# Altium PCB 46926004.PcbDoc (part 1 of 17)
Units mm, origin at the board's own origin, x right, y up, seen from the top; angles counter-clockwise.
Board outline 250 x 200 mm, 6 copper layers (Top Layer, INT1_GND, INT2_SIG, INT3_SIG, INT4_GND, Bottom Layer), stack 1.71 mm thick; 1450 components, 1293 nets, 5656 pads, 2307 vias.
Unrouted connection lines stored in the file: 2.
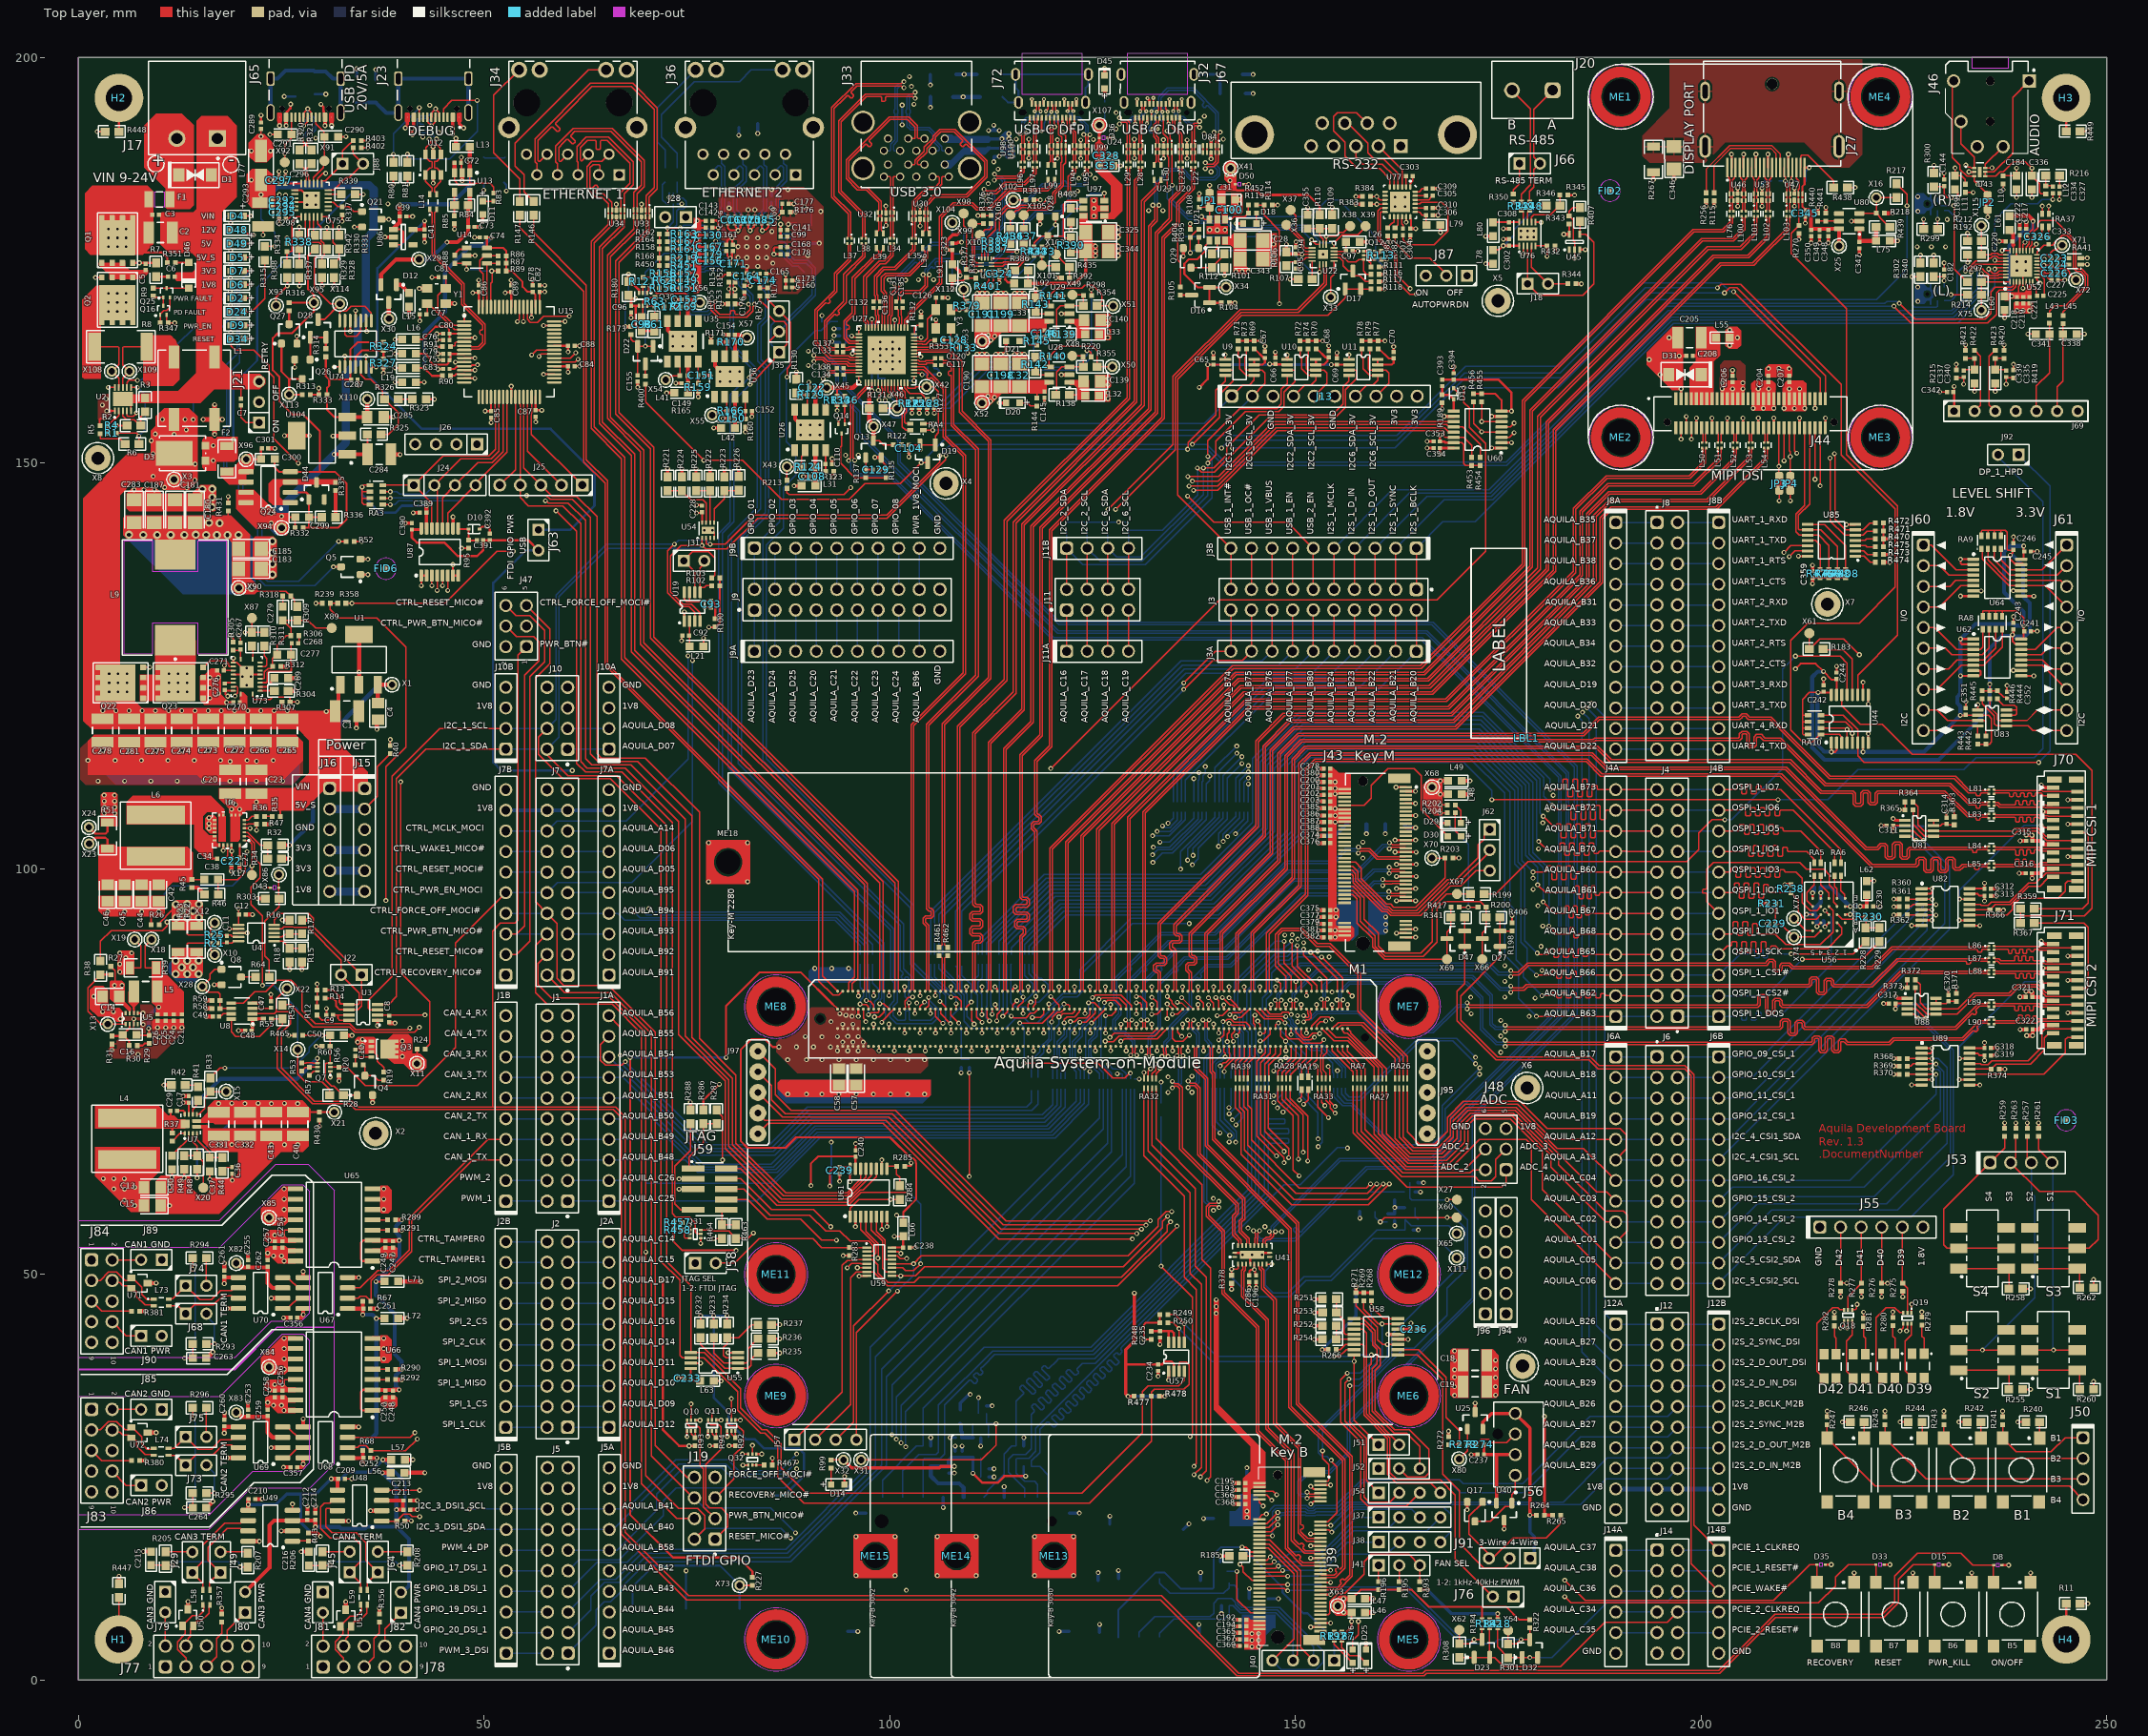
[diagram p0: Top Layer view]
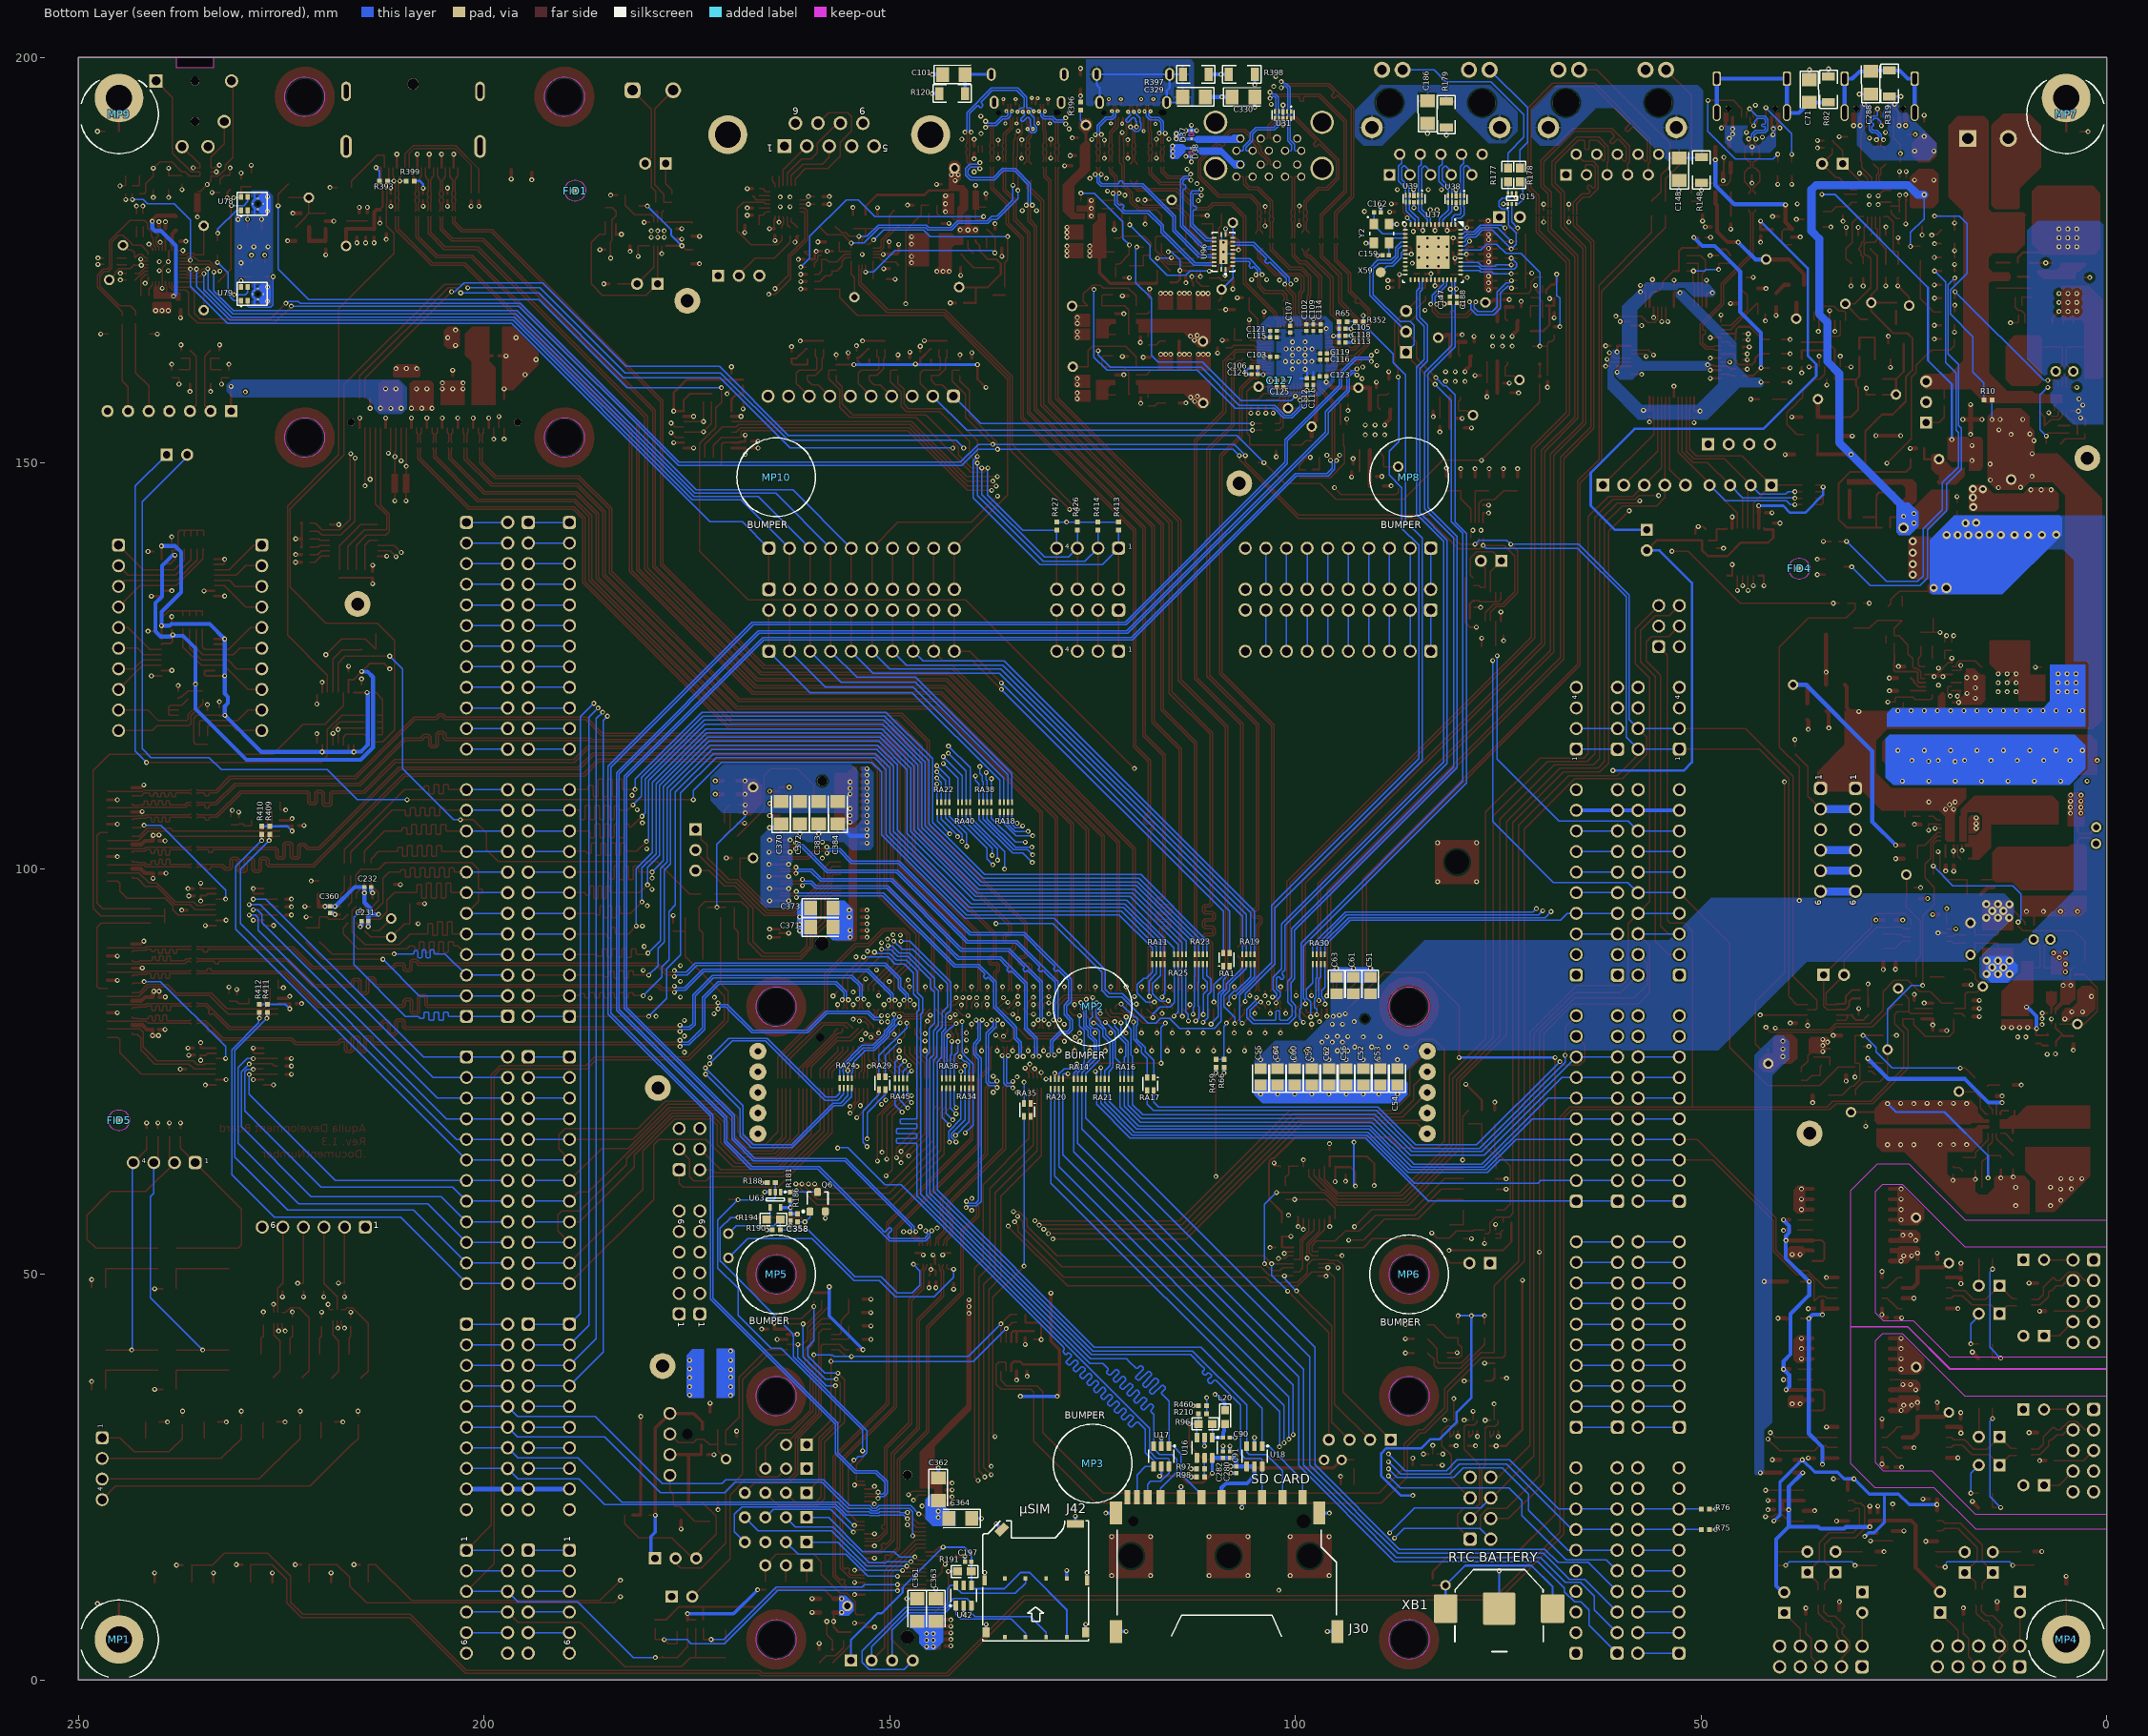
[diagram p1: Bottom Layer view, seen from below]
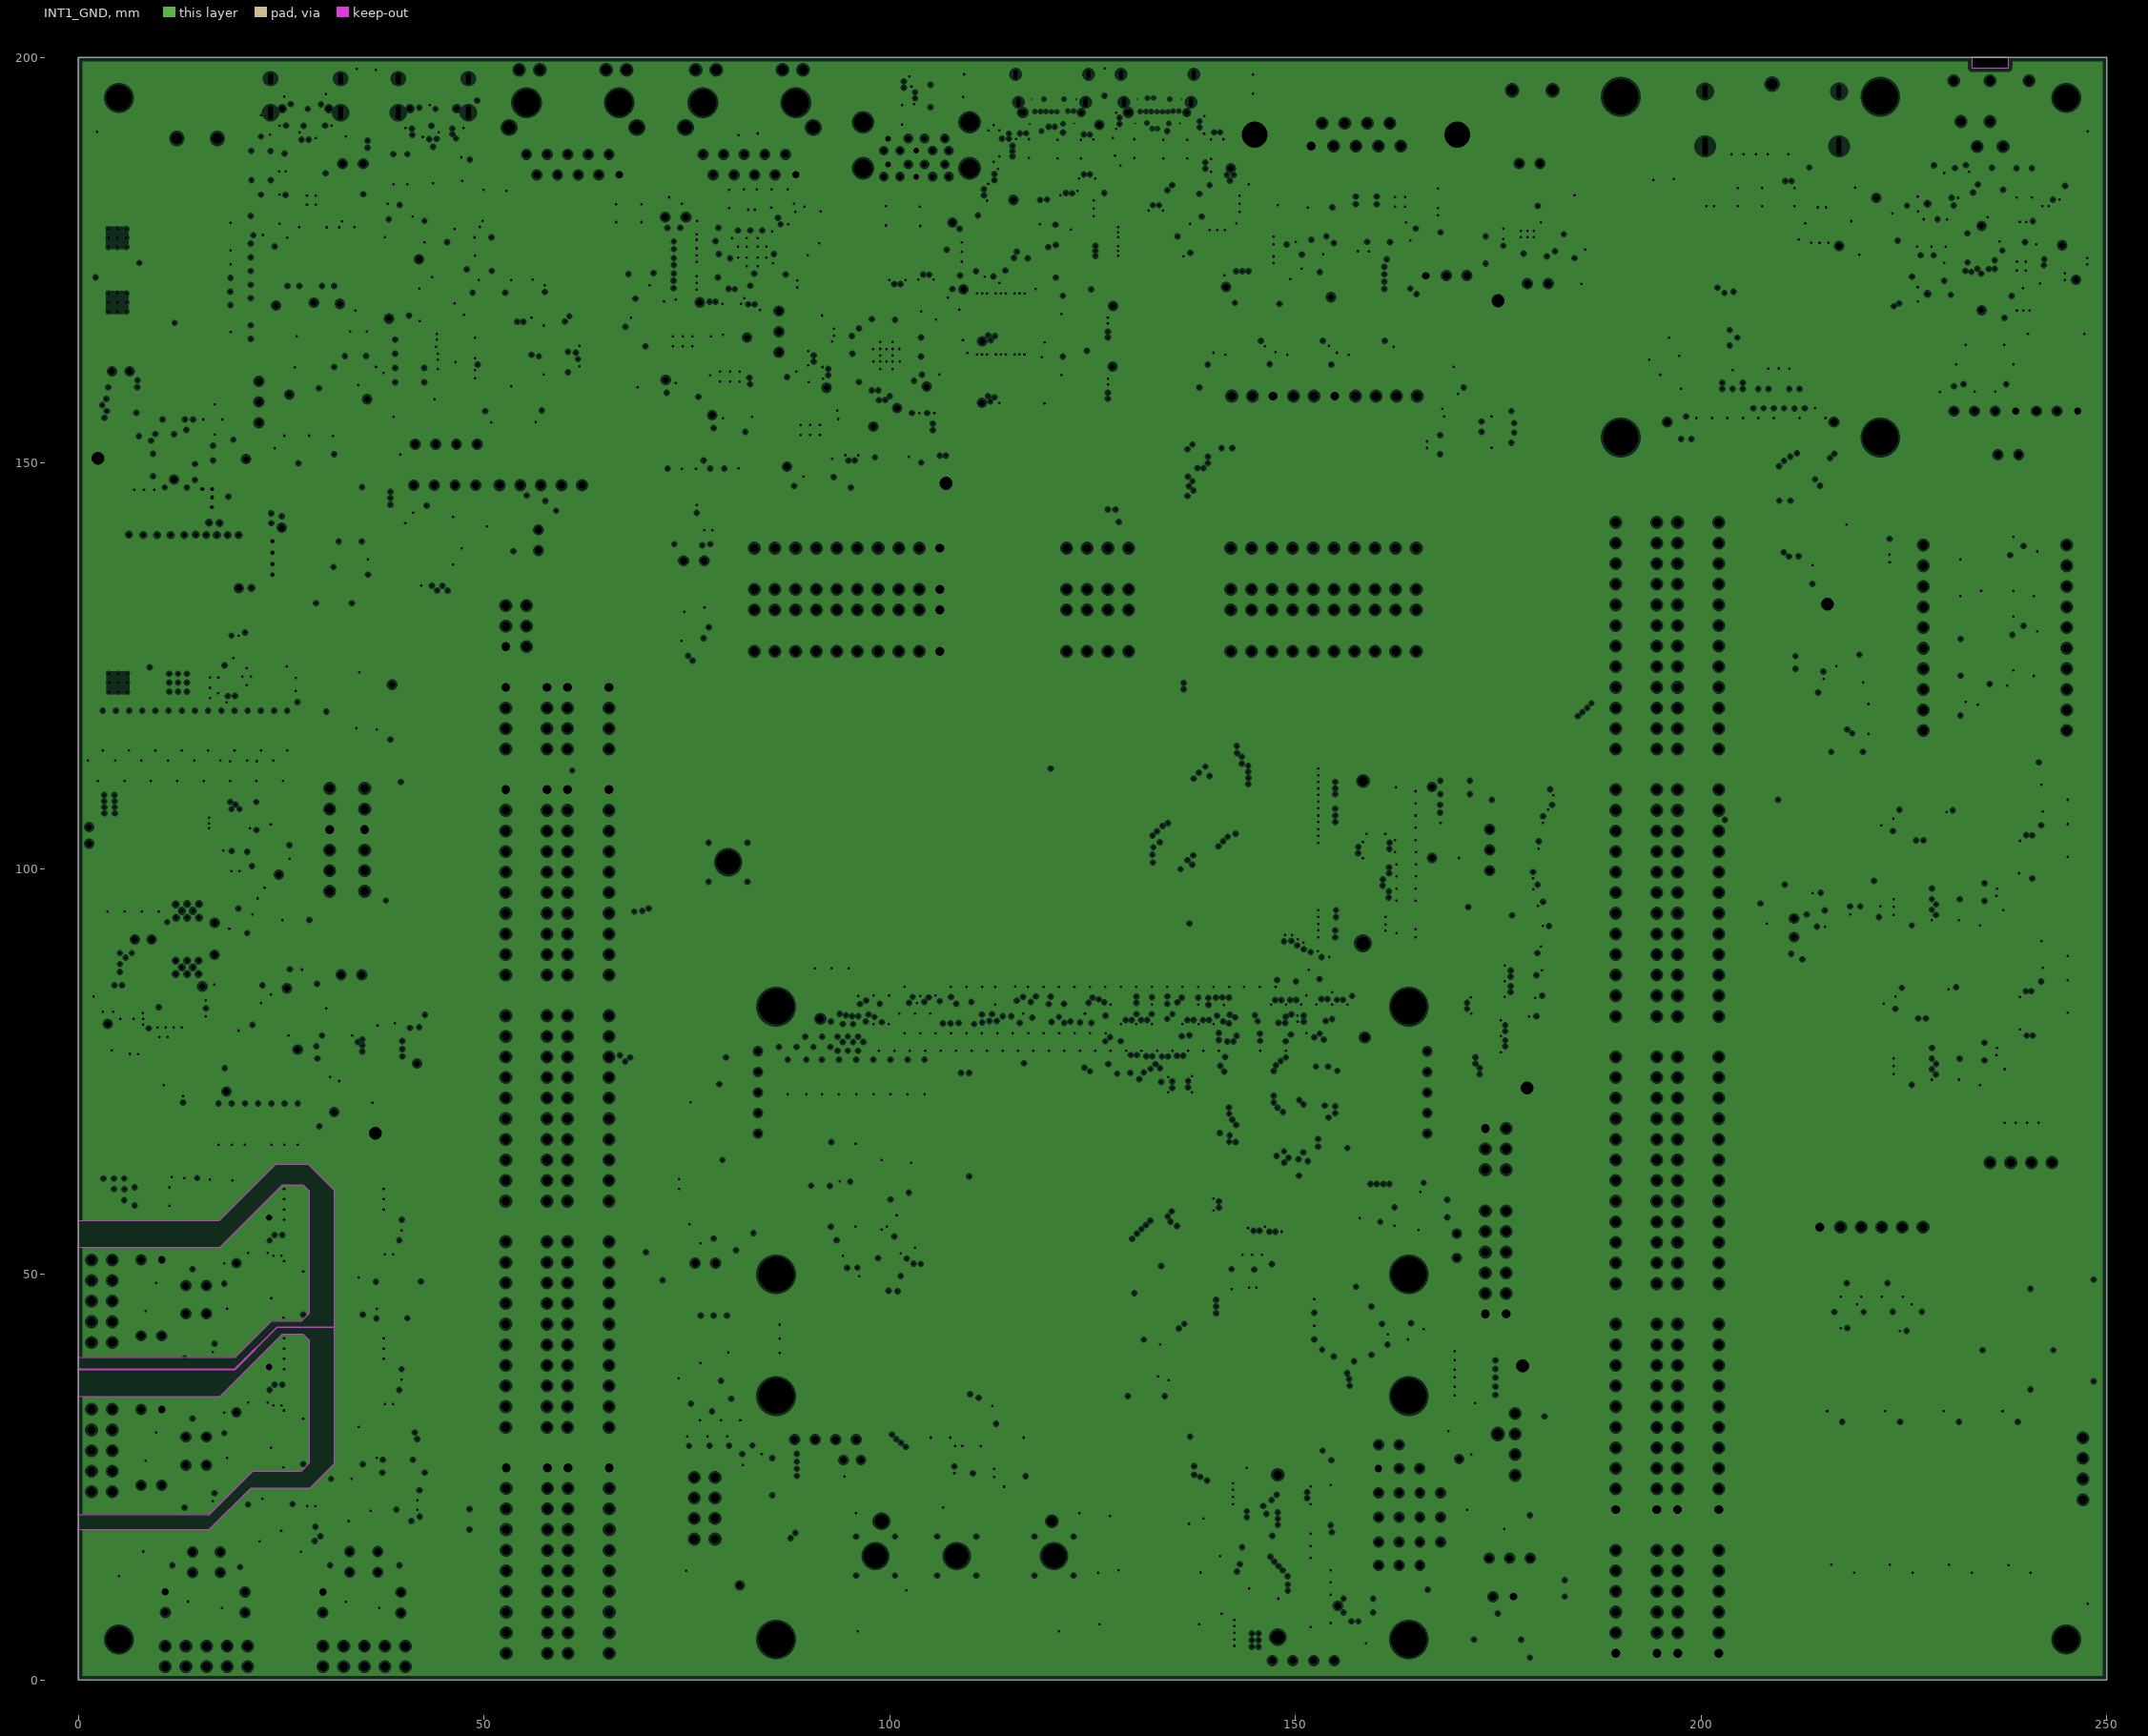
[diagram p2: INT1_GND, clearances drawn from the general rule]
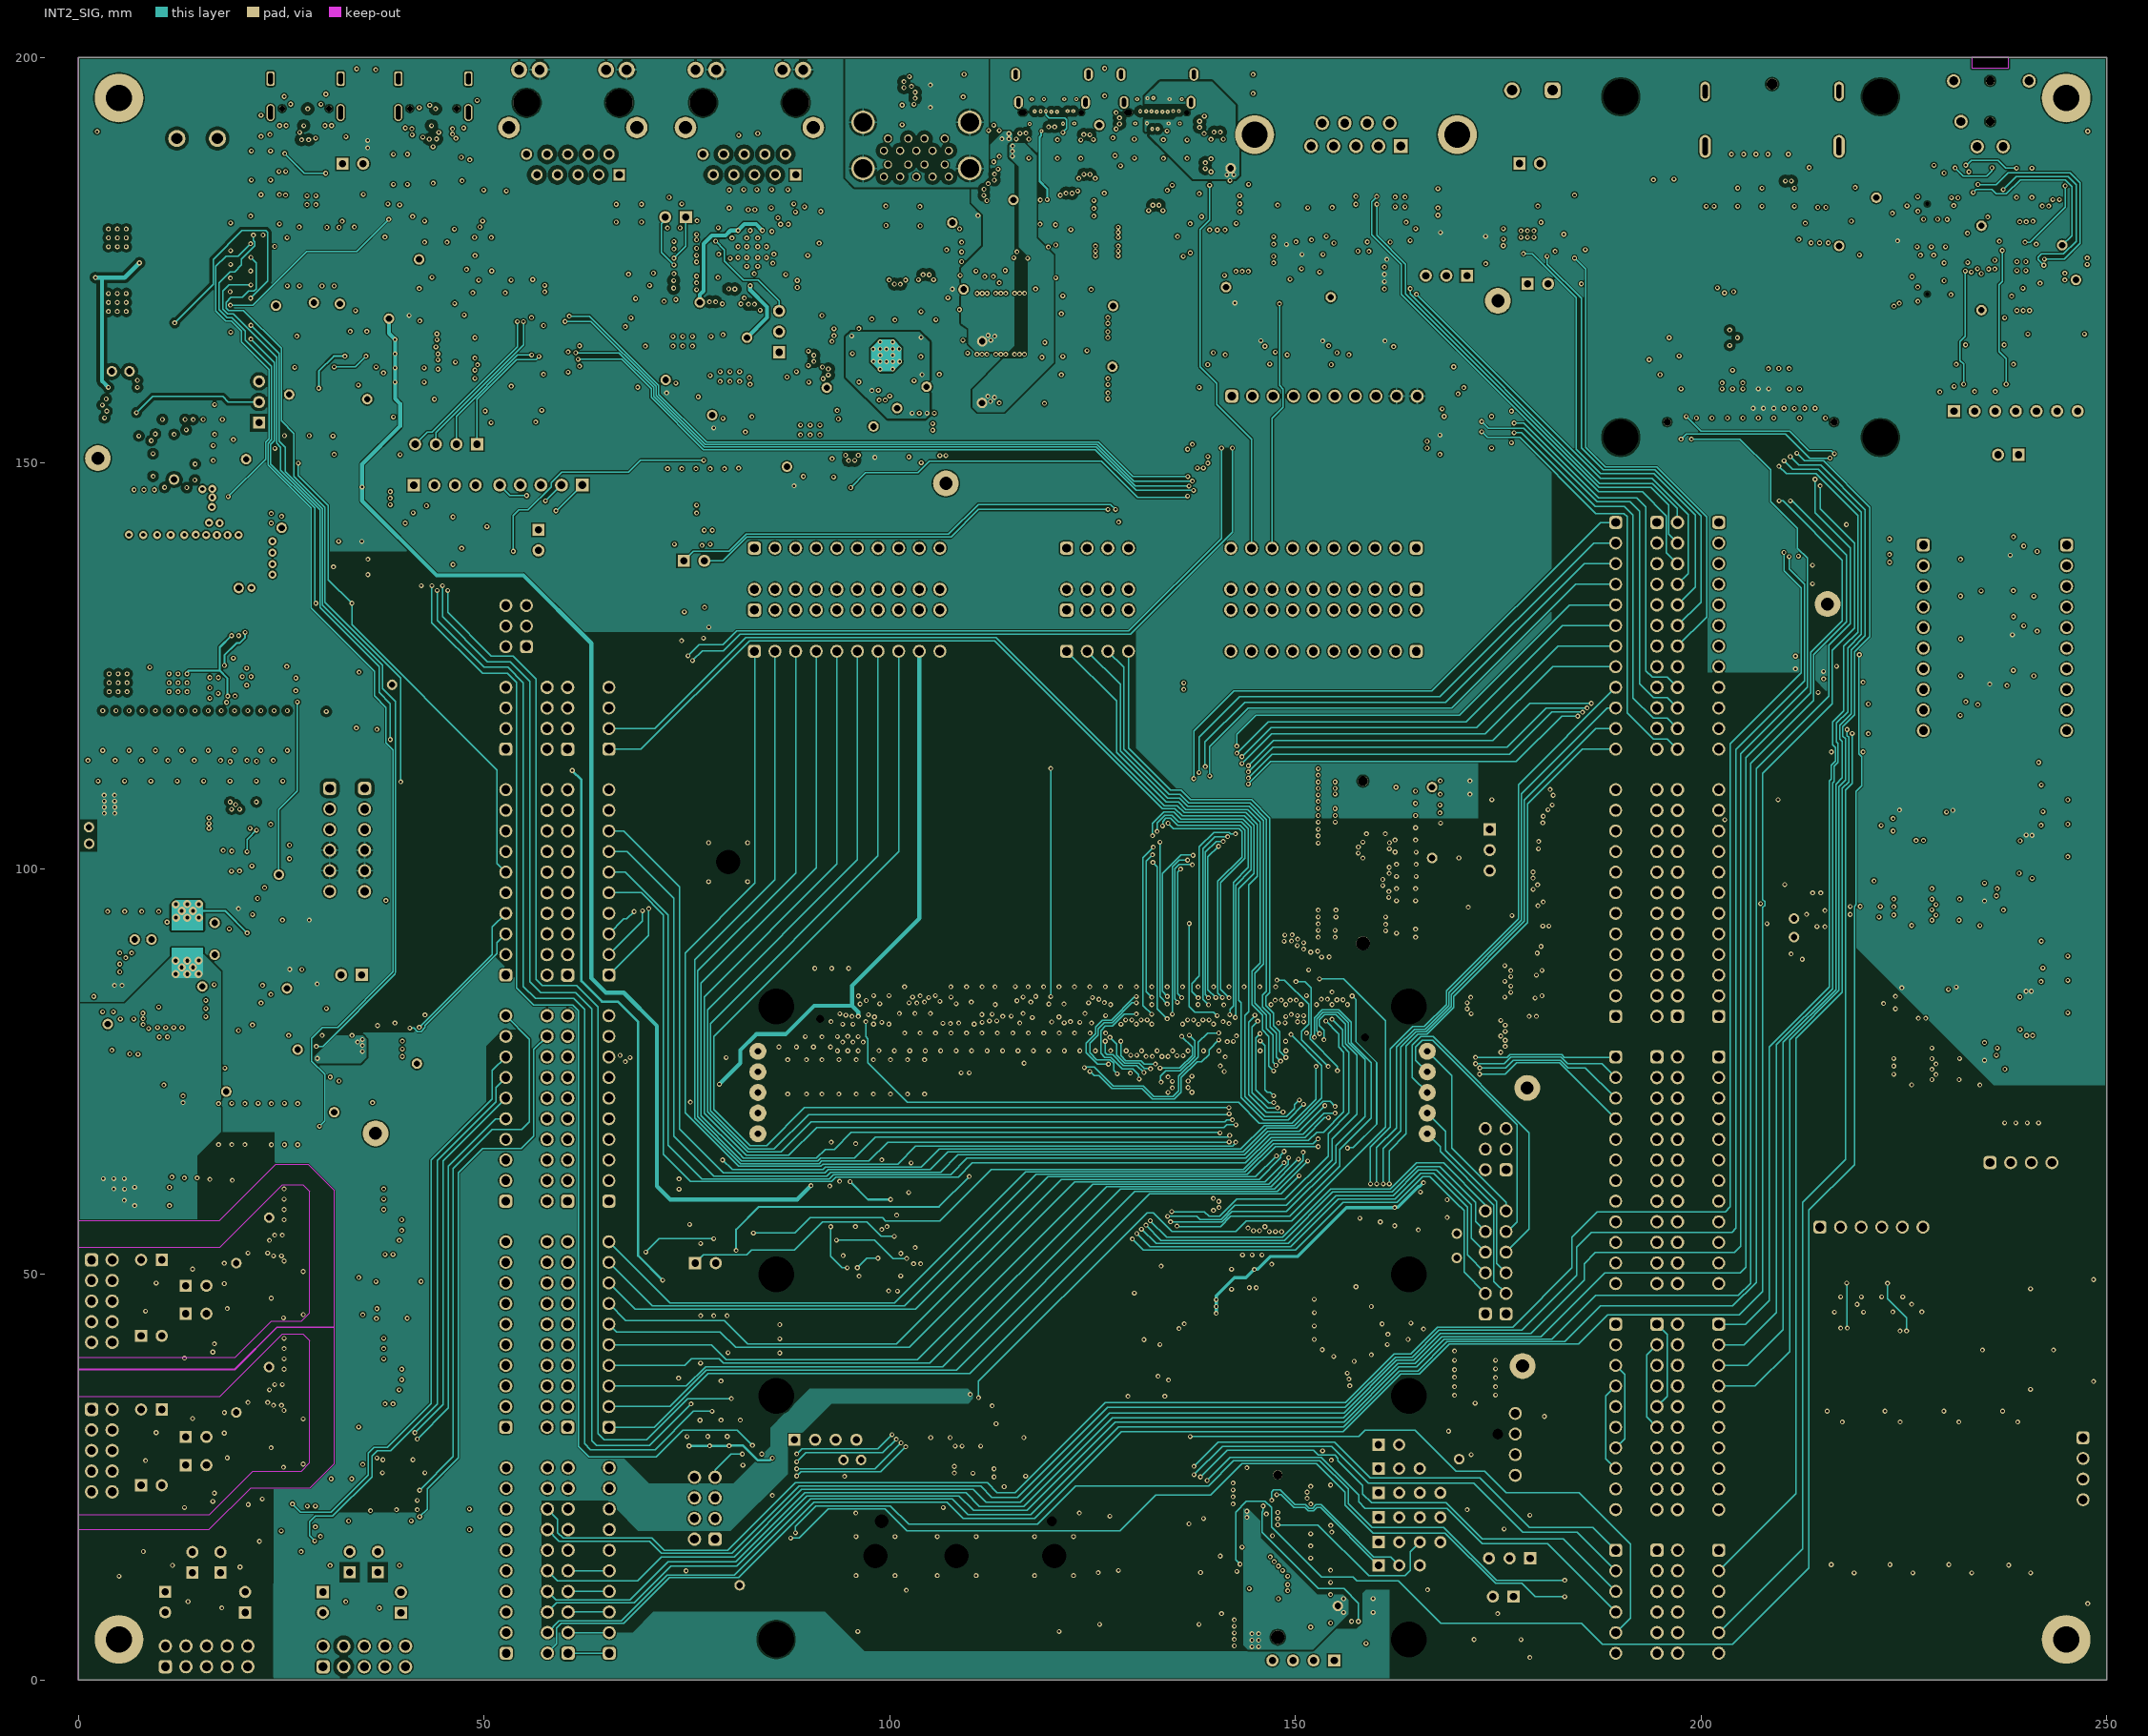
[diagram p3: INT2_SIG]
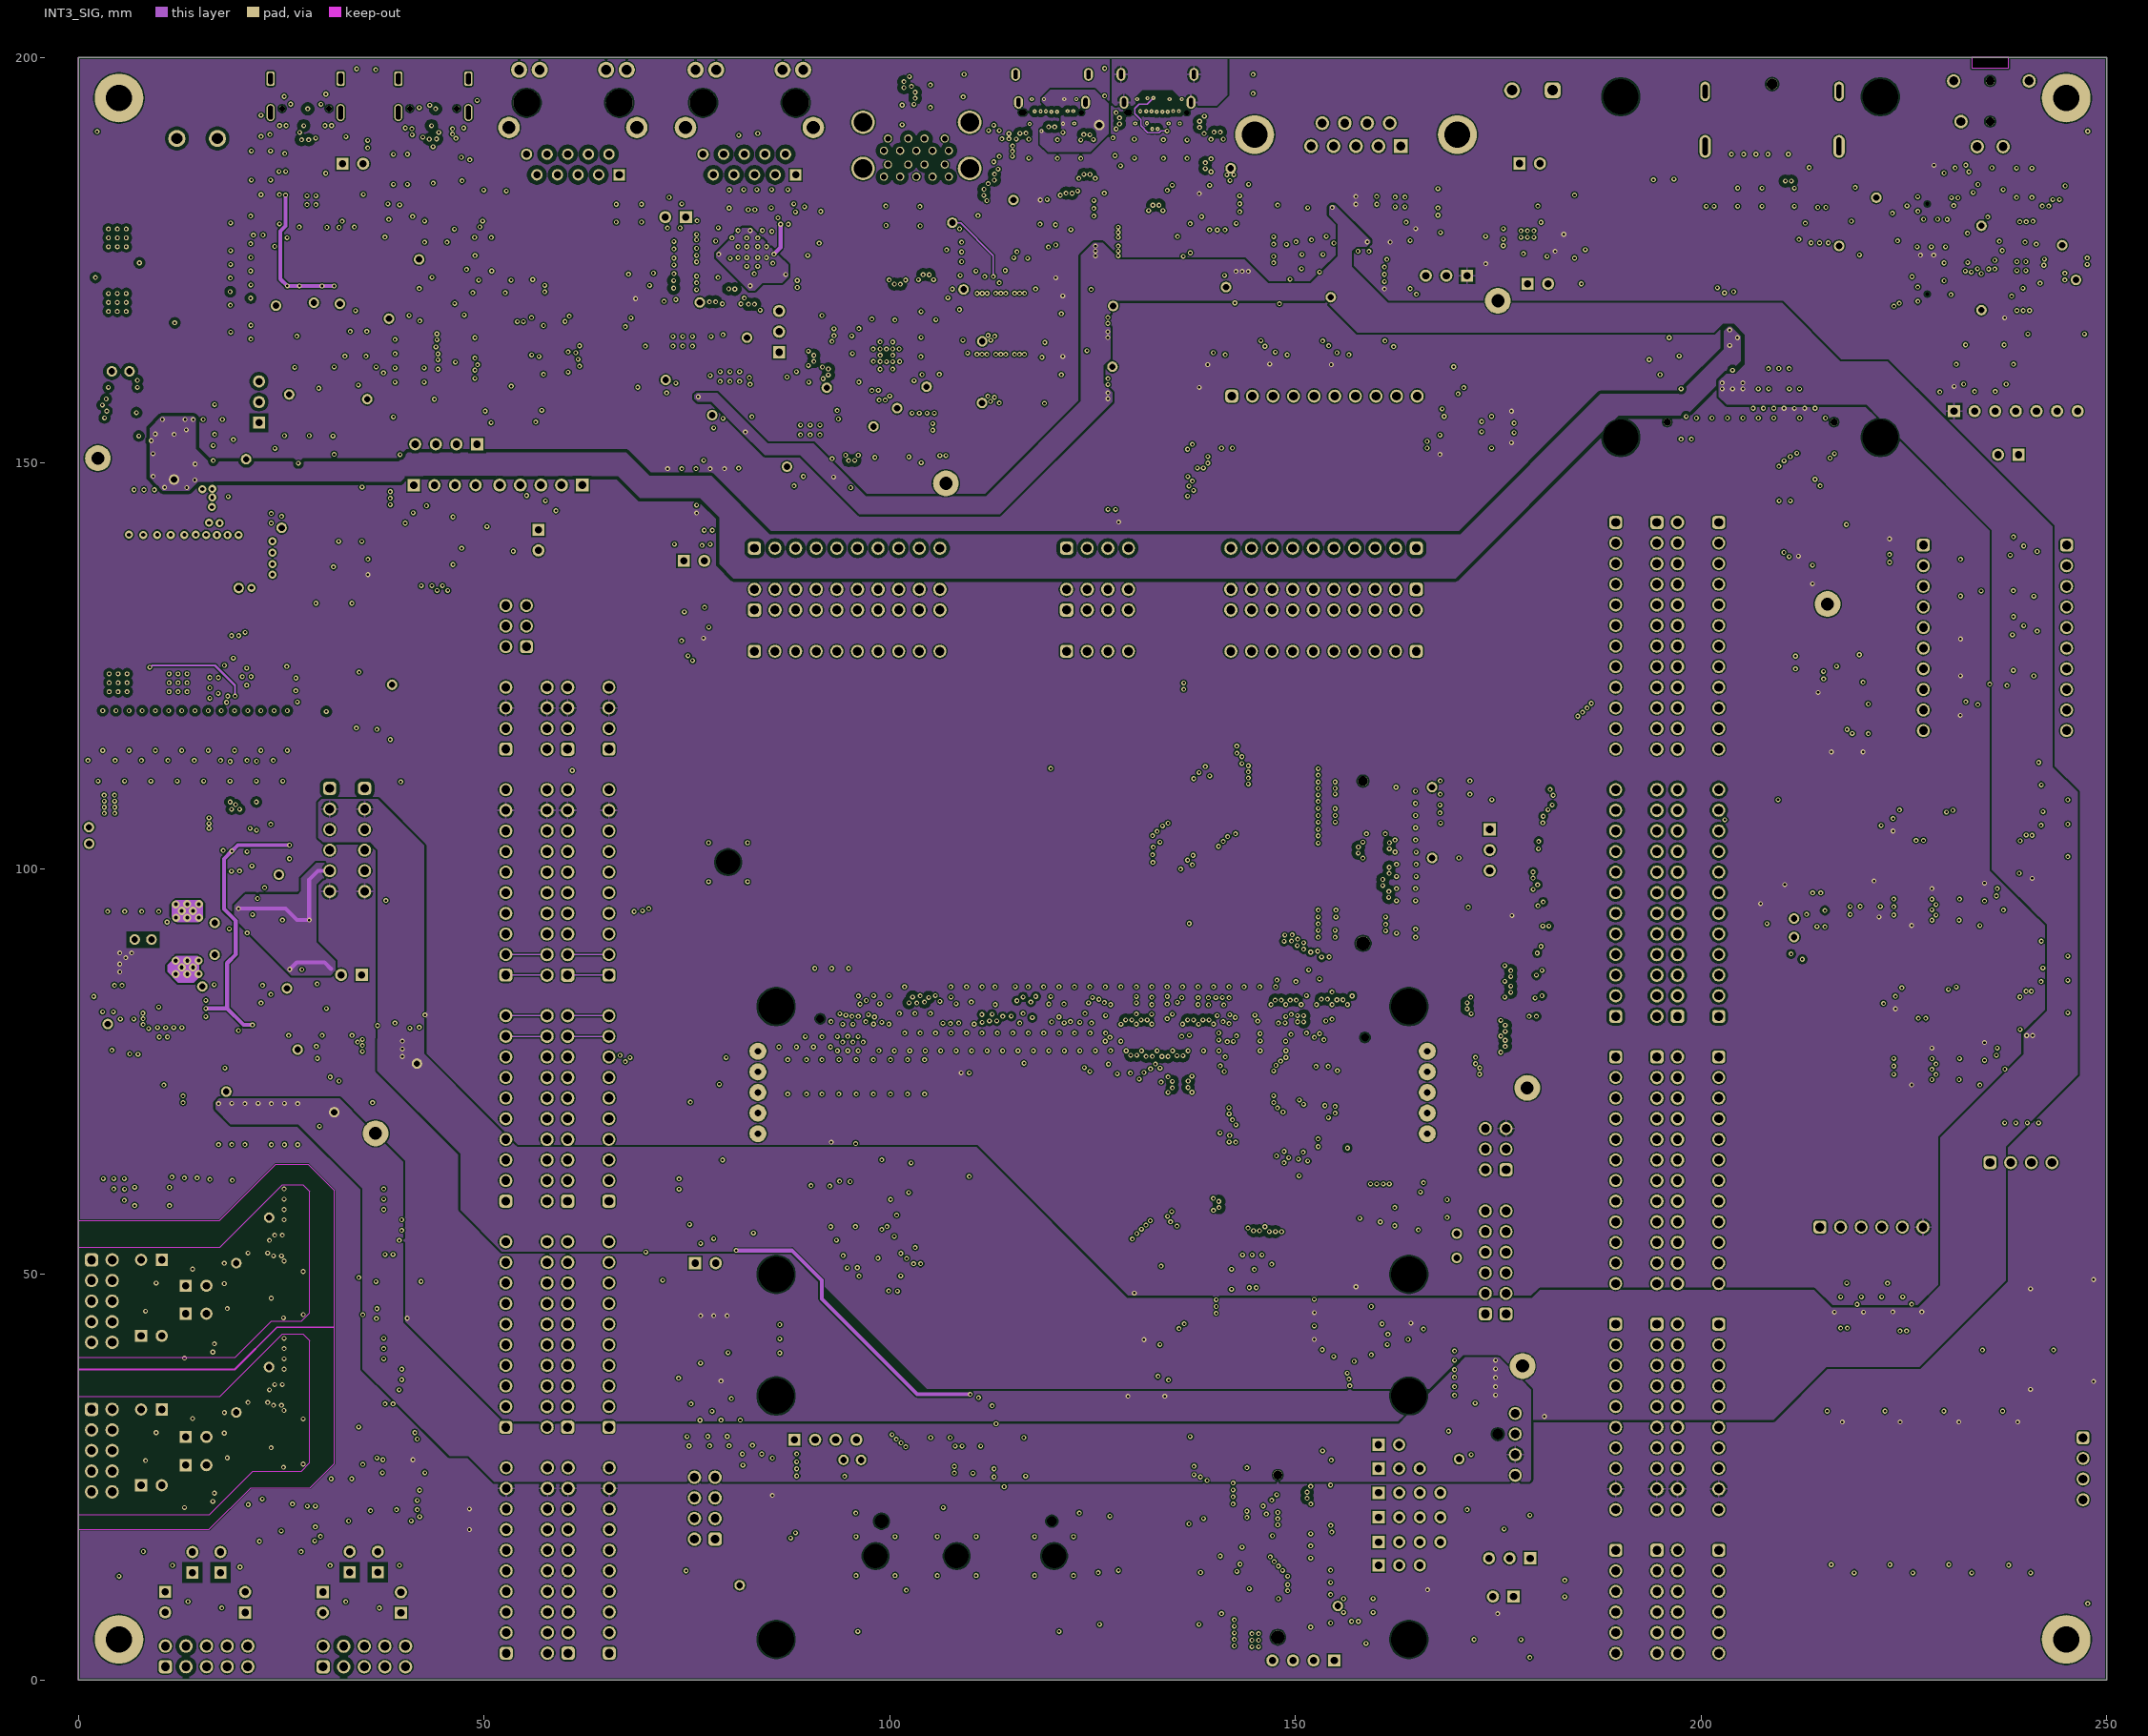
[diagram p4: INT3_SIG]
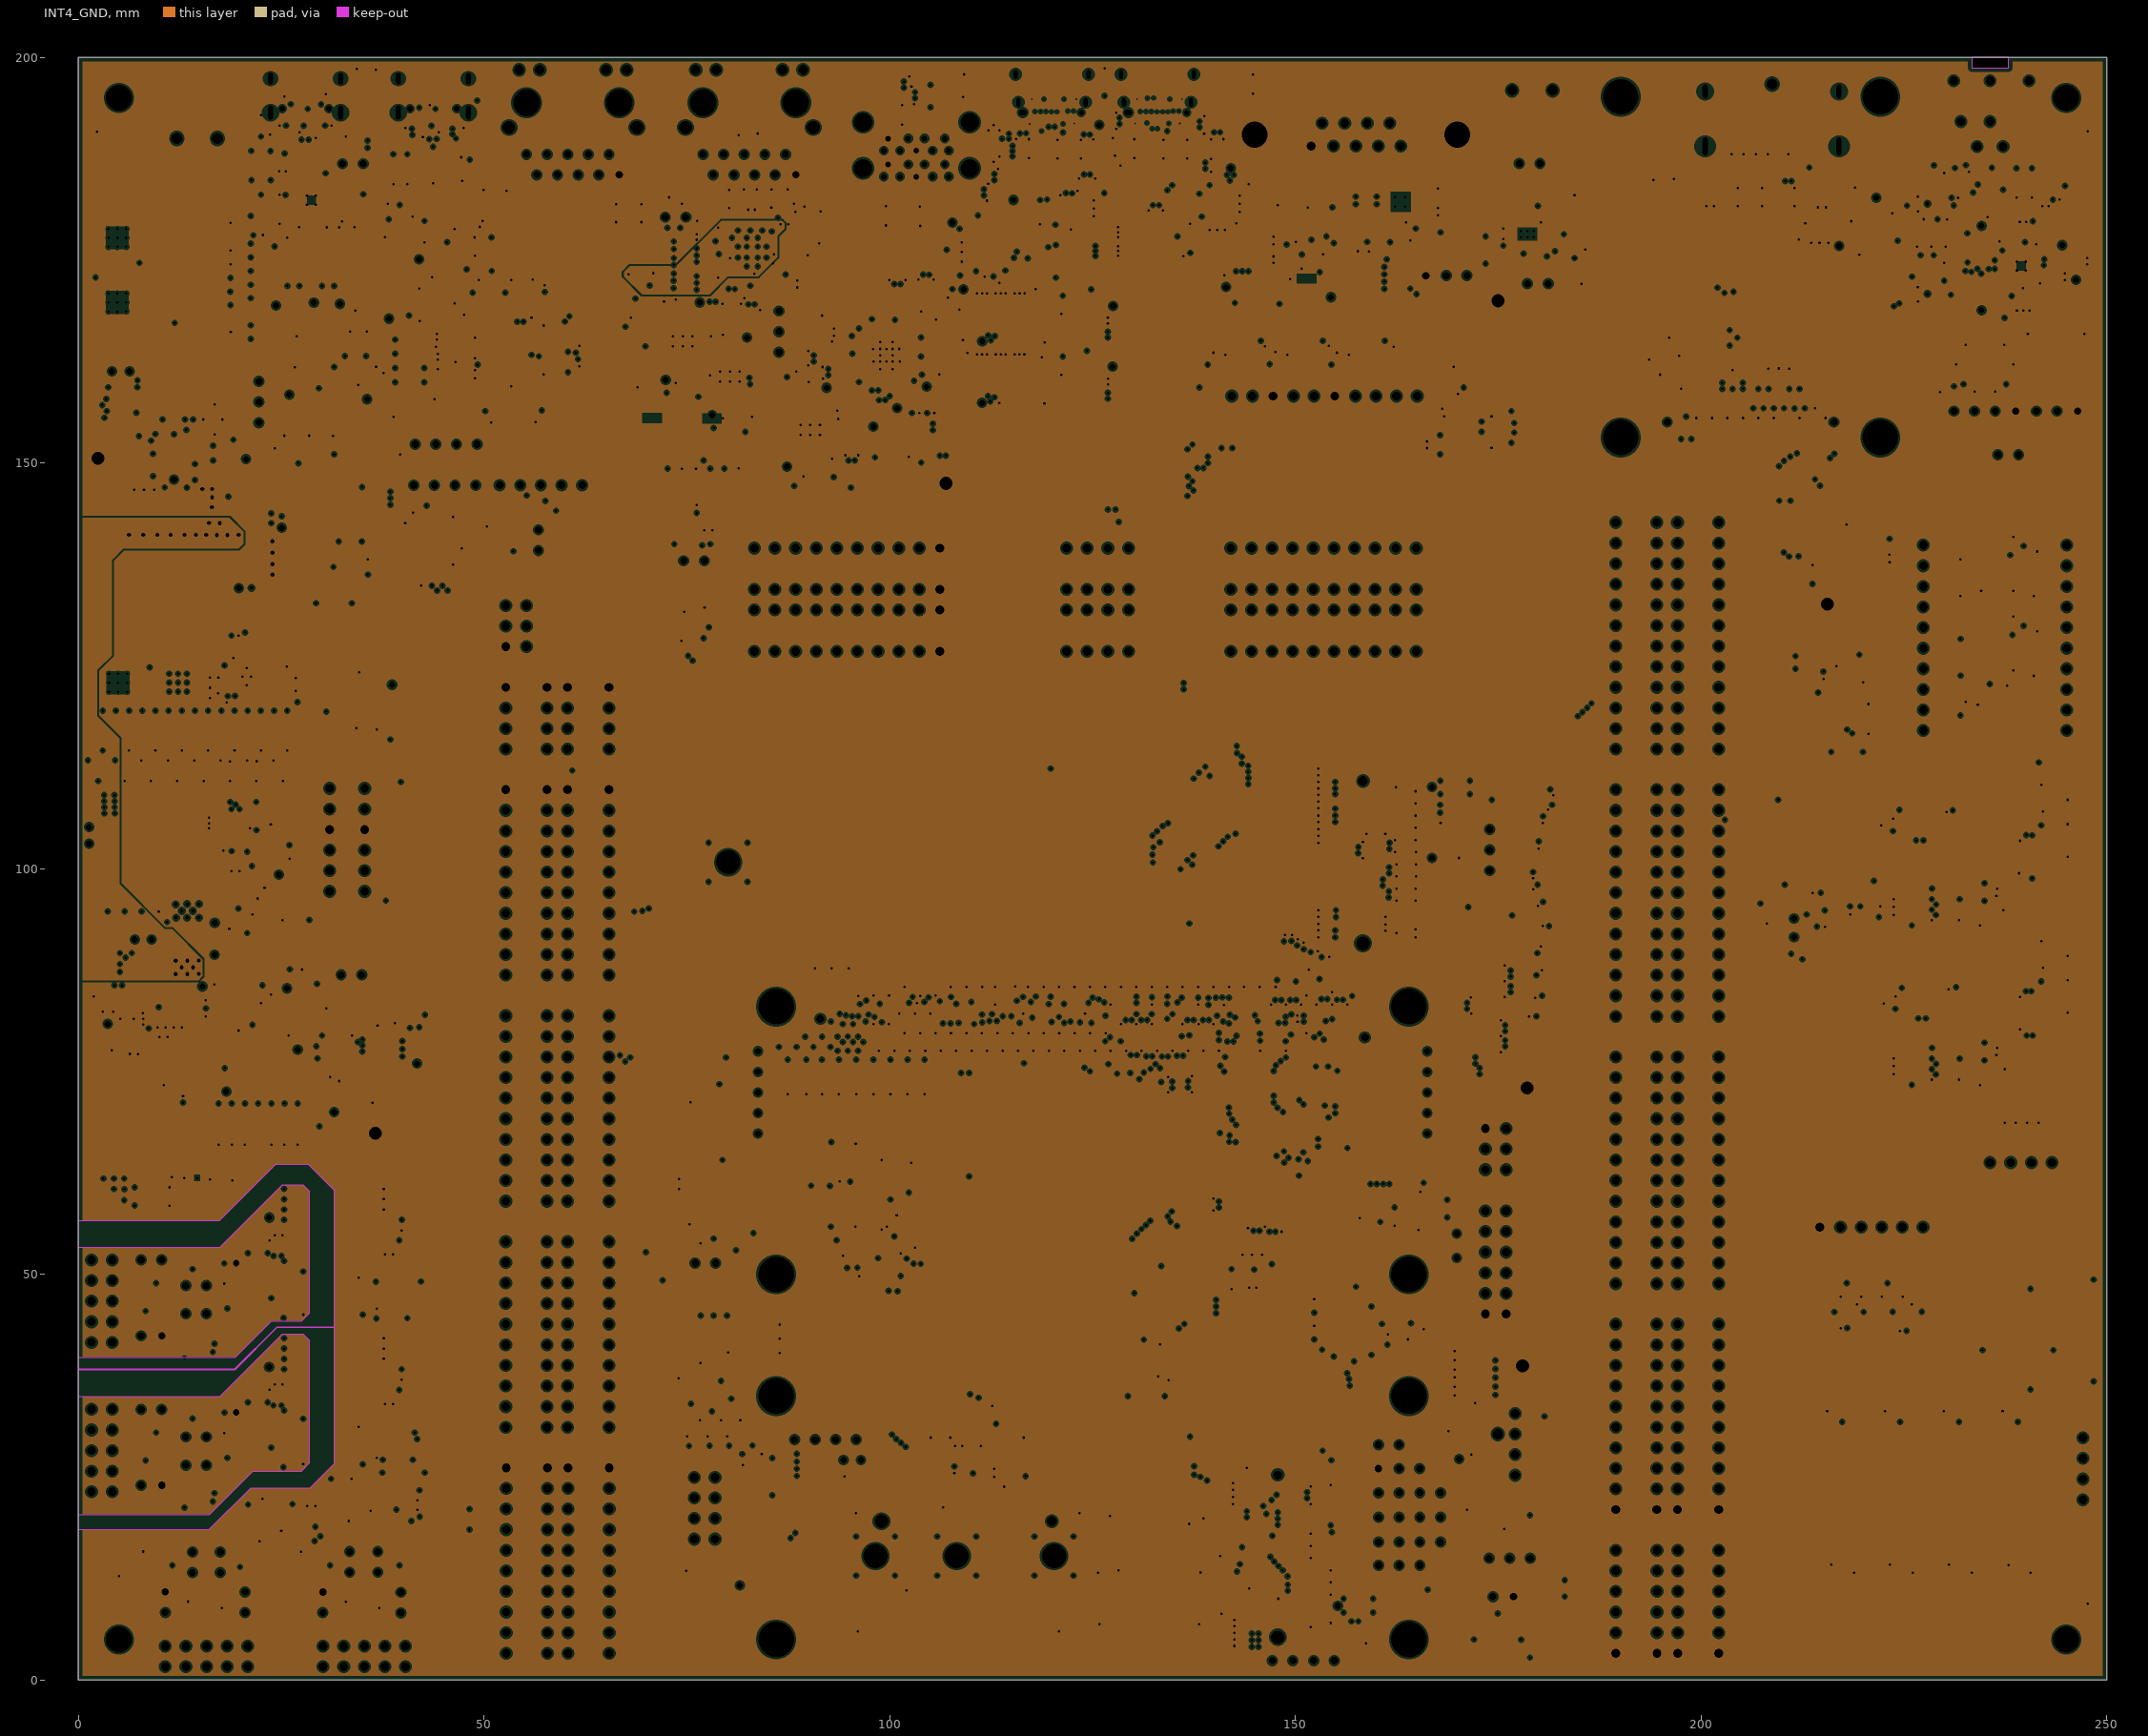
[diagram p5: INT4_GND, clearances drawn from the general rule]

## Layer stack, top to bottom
Top Solder: solder mask 0.02, Solder Resist, Dk 4.2
Top Layer: signal copper 0.035
Dielectric1: prepreg 0.1, FR-4, Dk 4.2
INT1_GND: plane copper 0.035, net (Multiple Nets)
Dielectric2: dielectric 0.15, FR-4, Dk 4.2
INT2_SIG: signal copper 0.035
Dielectric3: core 1, FR-4, Dk 4.2
INT3_SIG: signal copper 0.035
Dielectric 4: prepreg 0.15, FR-4, Dk 4.2
INT4_GND: plane copper 0.035, net (Multiple Nets)
Dielectric 5: prepreg 0.1, FR-4, Dk 4.2
Bottom Layer: signal copper 0.035
Bottom Solder: solder mask 0.02, Solder Resist, Dk 4.2

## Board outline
250,200 250,0 0,0 0,200
cut-out: 233.375,200 233.375,198.7 237.875,198.7 237.875,200

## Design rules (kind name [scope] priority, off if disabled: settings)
BoardOutlineClearance BoardOutlineClearance_Overlay [OnLayer('Top Overlay')] p1: gap=0.2 ignorepadtopadclearanceinfootprint=FALSE except(0.15: Arc-OutlineEdge Track-OutlineEdge)
BoardOutlineClearance [All] p2: gap=0.254 ignorepadtopadclearanceinfootprint=FALSE except(0: Arc-SplitContinuation Track-SplitContinuation SMDPad-SplitContinuation THPad-SplitContinuation Via-SplitContinuation Fill-SplitContinuation Poly-SplitContinuation Region-SplitContinuation Text-SplitContinuation)
Clearance Clearance_QSPI_Footprint [HasFootprint('T-PBGA-24')] p1: gap=0.15 ignorepadtopadclearanceinfootprint=TRUE except(0.5: Arc-Fill Arc-Poly Arc-Region Track-Fill Track-Poly Track-Region SMDPad-Fill SMDPad-Poly SMDPad-Region THPad-Fill THPad-Poly THPad-Region Via-Fill Via-Poly Via-Region Fill-Fill Fill-Poly Fill-Region Poly-Poly Poly-Region Region-Region)
Clearance "Clearance_Polygon - high speed 50R" [IsRegion vs InNetClass('50R')] p2: gap=0.15 ignorepadtopadclearanceinfootprint=TRUE except(0.3: Arc-Fill Arc-Poly Arc-Region Track-Fill Track-Poly Track-Region SMDPad-Fill SMDPad-Poly SMDPad-Region THPad-Fill THPad-Poly THPad-Region Via-Fill Via-Poly Via-Region Fill-Fill Fill-Poly Fill-Region Poly-Poly Poly-Region Region-Region)
Clearance "Clearance_Polygon - high speed 50R_SAME" [InNetClass('50R') vs InNetClass('50R')] p3: gap=0.3 ignorepadtopadclearanceinfootprint=TRUE except(0.15: Arc-SMDPad Arc-Via Track-SMDPad Track-Via SMDPad-SMDPad)
Clearance "Clearance_Polygon - Diff.Pairs" [IsRegion vs (InDifferentialPairClass('All Differential Pairs')) and NOT (InDifferentialPairClass('MSP'))] p4: gap=0.15 ignorepadtopadclearanceinfootprint=TRUE except(0.5: Arc-Fill Arc-Poly Arc-Region Track-Fill Track-Poly Track-Region SMDPad-Fill SMDPad-Poly SMDPad-Region THPad-Fill THPad-Poly THPad-Region Via-Fill Via-Poly Via-Region Fill-Fill Fill-Poly Fill-Region Poly-Poly Poly-Region Region-Region)
Clearance Clearance_HV_F1 [InNetClass('HV') vs HasFootprint('FUSE_1206_(3216)')] p5: gap=0.15 ignorepadtopadclearanceinfootprint=TRUE except(0.4: Arc-Fill Arc-Poly Arc-Region Track-Fill Track-Poly Track-Region THPad-Fill THPad-Poly THPad-Region Via-Fill Via-Poly Via-Region)
Clearance Clearance_HV [InNetClass('HV')] p6: gap=0.15 ignorepadtopadclearanceinfootprint=TRUE except(0.4: Arc-Fill Arc-Poly Arc-Region Track-Fill Track-Poly Track-Region SMDPad-Fill SMDPad-Poly SMDPad-Region THPad-Fill THPad-Poly THPad-Region Via-Fill Via-Poly Via-Region Fill-Fill Fill-Poly Fill-Region Poly-Poly Poly-Region Region-Region)
Clearance Clearance_Common [All] p7: gap=0.15 ignorepadtopadclearanceinfootprint=FALSE except(0.2: Arc-Hole Track-Hole SMDPad-Hole THPad-Hole Via-Hole Fill-Hole Poly-Hole Region-Hole Text-Hole; 0.25: Fill-Fill Fill-Poly Fill-Region Poly-Poly Poly-Region Region-Region)
ComponentClearance ComponentClearance_J57 [InComponent('J57') vs (InComponent('X31') OR InComponent('X32'))] p1: gap=-1 collisioncheckmode=3 verticalgap=0 showdistances=FALSE
ComponentClearance ComponentClearance_Pogo [(InComponent('M1') OR InComponent('J95') OR InComponent('J97'))] p2: gap=-1 collisioncheckmode=3 verticalgap=-1 showdistances=FALSE // Solves a conflict with 3D model of SOM
ComponentClearance [All] p3: gap=0 collisioncheckmode=3 verticalgap=0 showdistances=FALSE
DiffPairsRouting DiffPairsRouting_DSI [InDifferentialPairClass('DSI')   or  InDifferentialPairClass('DSI_1')    or InDifferentialPairClass('DSI_1_CON')] p1: maxlimit=0.2 minlimit=0.15 mostfreqgap=0.2 toplayer_maxgap=0.15 toplayer_prefgap=0.15 toplayer_minwidth=0.15 toplayer_maxwidth=0.15 toplayer_prefwidth=0.15 bottomlayer_maxgap=0.15 bottomlayer_prefgap=0.15 bottomlayer_minwidth=0.15 bottomlayer_maxwidth=0.15 bottomlayer_prefwidth=0.15 impedanceprofiledriven=TRUE impedanceprofileid={5D6EC751-2979-409B-BF7A-ED53235409C8} impedanceprofilevalue=90.000000 maxuncoupledlength=12.7
DiffPairsRouting DiffPairsRouting_CSI [InDifferentialPairClass('CSI') or InDifferentialPairClass('CSI_1') or InDifferentialPairClass('CSI_1_CON') or InDifferentialPairClass('CSI_2')  or InDifferentialPairClass('CSI_2_CON')] p2: maxlimit=0.2 minlimit=0.15 mostfreqgap=0.2 toplayer_maxgap=0.15 toplayer_prefgap=0.15 toplayer_minwidth=0.15 toplayer_maxwidth=0.15 toplayer_prefwidth=0.15 bottomlayer_maxgap=0.15 bottomlayer_prefgap=0.15 bottomlayer_minwidth=0.15 bottomlayer_maxwidth=0.15 bottomlayer_prefwidth=0.15 impedanceprofiledriven=TRUE impedanceprofileid={5D6EC751-2979-409B-BF7A-ED53235409C8} impedanceprofilevalue=90.000000 maxuncoupledlength=12.7
DiffPairsRouting DiffPairsRouting_USB_FTDI [InDifferentialPairClass('USB_FT_CON')] p3: maxlimit=0.2 minlimit=0.15 mostfreqgap=0.2 toplayer_maxgap=0.15 toplayer_prefgap=0.15 toplayer_minwidth=0.15 toplayer_maxwidth=0.15 toplayer_prefwidth=0.15 bottomlayer_maxgap=0.15 bottomlayer_prefgap=0.15 bottomlayer_minwidth=0.15 bottomlayer_maxwidth=0.15 bottomlayer_prefwidth=0.15 impedanceprofiledriven=TRUE impedanceprofileid={5D6EC751-2979-409B-BF7A-ED53235409C8} impedanceprofilevalue=90.000000 maxuncoupledlength=14 // Extended Uncoupled Length (connector)
DiffPairsRouting DiffPairsRouting_USB [InDifferentialPairClass('USB') or InDifferentialPairClass('USB_1') or InDifferentialPairClass('USB_1_CON') or InDifferentialPairClass('USB_1_SBU') or InDifferentialPairClass('USB_2') or InDifferentialPairClass('USB_2_SS') or InDifferentialPairClass('USB_2_SSTX')  or InDifferentialPairClass('USB_2_SS_HUB') or InDifferentialPairClass('USB_3') or InDifferentialPairClass('USB_3_CON')   or InDifferentialPairClass('USB_3_SS_HUB') or InDifferentialPairClass('USB_3_SSRX') or InDifferentialPairClass('USB_3_SSTX')   or InDifferentialPairClass('USB_3_MUX_SS1')  or InDifferentialPairClass('USB_3_MUX_SS2') or InDifferentialPairClass('USB_4')   or InDifferentialPairClass('USB_4_CON')   or InDifferentialPairClass('USB_4_SS') or InDifferentialPairClass('USB_4_SSTX') or InDifferentialPairClass('USB_4_SS_HUB')  or InDifferentialPairClass('USB_5')   or InDifferentialPairClass('USB_5_SS')    or InDifferentialPairClass('USB_5_CON')        or InDifferentialPairClass('USB_5_SSTX')  or InDifferentialPairClass('USB_5_SS_HUB')   or InDifferentialPairClass('USB_5')  or InDifferentialPairClass('USB_6')     or InDifferentialPairClass('USB_6_SS') or InDifferentialPairClass('USB_6_SSTX')     or InDifferentialPairClass('USB_6_SS_HUB')    or InDifferentialPairClass('USB_CYP')    or InDifferentialPairClass('USB_FT')     or InDifferentialPairClass('USB_FT_CON') or  InDifferentialPairClass('HS_USB')     or InDifferentialPairClass('HS_USB_3')    or InDifferentialPairClass('HS_USB1') or  InDifferentialPairClass('USB_6_SSRX')  or  InDifferentialPairClass('USB_5_SSRX') or  InDifferentialPairClass('USB_4_SSRX')  or  InDifferentialPairClass('USB_3_SSRX') or  InDifferentialPairClass('USB_2_SSRX')  or  InDifferentialPairClass('SSTX2')   or  InDifferentialPairClass('SSTX1')   or  InDifferentialPairClass('SSRX2')   or  InDifferentialPairClass('SSRX1')   or  InDifferentialPairClass('USB_2_SSTX_HUB')  or InDifferentialPairClass('USB_4_SS_CON') or InDifferentialPairClass('USB_5_SS_CON')] p4: maxlimit=0.2 minlimit=0.15 mostfreqgap=0.2 toplayer_maxgap=0.15 toplayer_prefgap=0.15 toplayer_minwidth=0.15 toplayer_maxwidth=0.15 toplayer_prefwidth=0.15 bottomlayer_maxgap=0.15 bottomlayer_prefgap=0.15 bottomlayer_minwidth=0.15 bottomlayer_maxwidth=0.15 bottomlayer_prefwidth=0.15 impedanceprofiledriven=TRUE impedanceprofileid={5D6EC751-2979-409B-BF7A-ED53235409C8} impedanceprofilevalue=90.000000 maxuncoupledlength=12.7
DiffPairsRouting DiffPairsRouting_DP [InDifferentialPairClass('DP')] p5: maxlimit=0.2 minlimit=0.15 mostfreqgap=0.2 toplayer_maxgap=0.15 toplayer_prefgap=0.15 toplayer_minwidth=0.15 toplayer_maxwidth=0.15 toplayer_prefwidth=0.15 bottomlayer_maxgap=0.15 bottomlayer_prefgap=0.15 bottomlayer_minwidth=0.15 bottomlayer_maxwidth=0.15 bottomlayer_prefwidth=0.15 impedanceprofiledriven=TRUE impedanceprofileid={5D6EC751-2979-409B-BF7A-ED53235409C8} impedanceprofilevalue=90.000000 maxuncoupledlength=12.7
DiffPairsRouting DiffPairsRouting_PCIe [InDifferentialPairClass('PCIe_1')  or InDifferentialPairClass('PCIe_2')] p6: maxlimit=0.2 minlimit=0.15 mostfreqgap=0.2 toplayer_maxgap=0.15 toplayer_prefgap=0.15 toplayer_minwidth=0.15 toplayer_maxwidth=0.15 toplayer_prefwidth=0.15 bottomlayer_maxgap=0.15 bottomlayer_prefgap=0.15 bottomlayer_minwidth=0.15 bottomlayer_maxwidth=0.15 bottomlayer_prefwidth=0.15 impedanceprofiledriven=TRUE impedanceprofileid={5D6EC751-2979-409B-BF7A-ED53235409C8} impedanceprofilevalue=90.000000 maxuncoupledlength=12.7
DiffPairsRouting DiffPairsRouting_PCIEUSB [InDifferentialPairClass('PCIEUSB')] p7: maxlimit=0.2 minlimit=0.15 mostfreqgap=0.2 toplayer_maxgap=0.15 toplayer_prefgap=0.15 toplayer_minwidth=0.15 toplayer_maxwidth=0.15 toplayer_prefwidth=0.15 bottomlayer_maxgap=0.15 bottomlayer_prefgap=0.15 bottomlayer_minwidth=0.15 bottomlayer_maxwidth=0.15 bottomlayer_prefwidth=0.15 impedanceprofiledriven=TRUE impedanceprofileid={5D6EC751-2979-409B-BF7A-ED53235409C8} impedanceprofilevalue=90.000000 maxuncoupledlength=12.7
DiffPairsRouting DiffPairsRouting_ETH_1 [InDifferentialPairClass('ETH1')] p8: maxlimit=0.25 minlimit=0.15 mostfreqgap=0.25 toplayer_mingap=0.25 toplayer_minwidth=0.15 toplayer_maxwidth=0.15 toplayer_prefwidth=0.15 bottomlayer_mingap=0.25 bottomlayer_minwidth=0.15 bottomlayer_maxwidth=0.15 bottomlayer_prefwidth=0.15 impedanceprofiledriven=TRUE impedanceprofileid={4A91EA07-8D62-4C1D-BC50-AFB5A511922E} impedanceprofilevalue=95.000000 maxuncoupledlength=12.7
DiffPairsRouting DiffPairsRouting_ETH_2 [InDifferentialPairClass('ETH2')] p9: maxlimit=0.25 minlimit=0.15 mostfreqgap=0.25 toplayer_mingap=0.25 toplayer_minwidth=0.15 toplayer_maxwidth=0.15 toplayer_prefwidth=0.15 bottomlayer_mingap=0.25 bottomlayer_minwidth=0.15 bottomlayer_maxwidth=0.15 bottomlayer_prefwidth=0.15 impedanceprofiledriven=TRUE impedanceprofileid={4A91EA07-8D62-4C1D-BC50-AFB5A511922E} impedanceprofilevalue=95.000000 maxuncoupledlength=12.7
DiffPairsRouting DiffPairsRouting_XGMII [InDifferentialPairClass('XGMII')] p10: maxlimit=0.25 minlimit=0.15 mostfreqgap=0.25 toplayer_mingap=0.25 toplayer_minwidth=0.15 toplayer_maxwidth=0.15 toplayer_prefwidth=0.15 bottomlayer_mingap=0.25 bottomlayer_minwidth=0.15 bottomlayer_maxwidth=0.15 bottomlayer_prefwidth=0.15 impedanceprofiledriven=TRUE impedanceprofileid={4A91EA07-8D62-4C1D-BC50-AFB5A511922E} impedanceprofilevalue=95.000000 maxuncoupledlength=12.7
DiffPairsRouting DiffPairsRouting_XGMII_PHY [InDifferentialPairClass('XGMII_PHY')] p11: maxlimit=0.25 minlimit=0.15 mostfreqgap=0.25 toplayer_mingap=0.25 toplayer_minwidth=0.15 toplayer_maxwidth=0.15 toplayer_prefwidth=0.15 bottomlayer_mingap=0.25 bottomlayer_minwidth=0.15 bottomlayer_maxwidth=0.15 bottomlayer_prefwidth=0.15 impedanceprofiledriven=TRUE impedanceprofileid={4A91EA07-8D62-4C1D-BC50-AFB5A511922E} impedanceprofilevalue=95.000000 maxuncoupledlength=12.7
DiffPairsRouting DiffPairsRouting_CAN [InDifferentialPairClass('CAN')] p12: maxlimit=0.5 minlimit=0.5 mostfreqgap=0.5 toplayer_minwidth=0.15 toplayer_maxwidth=0.15 toplayer_prefwidth=0.15 impedanceprofiledriven=TRUE impedanceprofileid={6AC87C16-5B82-43D3-AA7F-EDD5556BB168} impedanceprofilevalue=100.000000 maxuncoupledlength=12.7
FabricationTestPointUsage TestPointUsage [All] p1: valid=0 allowmultiple=FALSE
FabricationTestpoint Testpoint [All] p1: side=3 testpointundercomponent=TRUE minsize=1.016 maxsize=2.54 preferedsize=1.524 minholesize=0 maxholesize=1.016 preferedholesize=0.813 testpointgrid=0.025 allowsidetop=TRUE allowsidebottom=TRUE usegrid=TRUE gridtolerance=0
Height [All] p1: minheight=0 maxheight=69 prefheight=12.7
HoleSize [All] p1: absolutevalues=TRUE maxlimit=5 minlimit=0.1 maxpercent=80.000 minpercent=20.000
HoleToHoleClearance [All] p1: gap=0.25 allowstackedmicrovias=FALSE
MatchedLengths MatchLengths_xSignals_M1_J4 [InxSignalClass('xSignals_M1_J4_MatchLengthsClass')] p1: tolerance=2.54 checknetsindiffpair=FALSE checkdiffpairvsdiffpair=TRUE checkxsignals=TRUE checkothers=TRUE
MatchedLengths SPI [InNetClass('SPI')] p2: tolerance=25.4 checknetsindiffpair=FALSE checkdiffpairvsdiffpair=TRUE checkxsignals=TRUE checkothers=TRUE usedelayunits=TRUE delaytolerance=10.000000
MatchedLengths QSPIx [InxSignalClass('QSPIx')] p3: tolerance=25.4 checknetsindiffpair=FALSE checkdiffpairvsdiffpair=TRUE checkxsignals=TRUE checkothers=TRUE usedelayunits=TRUE delaytolerance=1.000000 targetsourcename=QSPI_1_SCK-NetJ4_8_PP1
MatchedLengths QSPIx_JMP [InxSignalClass('QSPI_JMP')] p4: tolerance=25.4 checknetsindiffpair=FALSE checkdiffpairvsdiffpair=TRUE checkxsignals=TRUE checkothers=TRUE usedelayunits=TRUE delaytolerance=1.000000 targetsourcename=QSPI_1_SCK_JMP_PP1
MatchedLengths SD [InNetClass('SD')] p5: tolerance=25.4 checknetsindiffpair=FALSE checkdiffpairvsdiffpair=TRUE checkxsignals=TRUE checkothers=TRUE usedelayunits=TRUE delaytolerance=20.000000
MatchedLengths CSI_1_pair [InDifferentialPairClass('CSI_1')  or InDifferentialPairClass('CSI_1_CON')] p6: tolerance=25.4 checknetsindiffpair=TRUE checkdiffpairvsdiffpair=FALSE checkxsignals=FALSE checkothers=FALSE usedelayunits=TRUE delaytolerance=1.000000
MatchedLengths CSI_1_group [InDifferentialPairClass('CSI_1')] p7: tolerance=25.4 checknetsindiffpair=FALSE checkdiffpairvsdiffpair=TRUE checkxsignals=TRUE checkothers=TRUE usedelayunits=TRUE delaytolerance=10.000000
MatchedLengths CSI_2_pair [InDifferentialPairClass('CSI_2')   or InDifferentialPairClass('CSI_2_CON')] p8: tolerance=25.4 checknetsindiffpair=TRUE checkdiffpairvsdiffpair=FALSE checkxsignals=FALSE checkothers=FALSE usedelayunits=TRUE delaytolerance=1.000000
MatchedLengths CSI_2_group [InDifferentialPairClass('CSI_2')] p9: tolerance=25.4 checknetsindiffpair=FALSE checkdiffpairvsdiffpair=TRUE checkxsignals=TRUE checkothers=TRUE usedelayunits=TRUE delaytolerance=10.000000
MatchedLengths DSI_pair [InDifferentialPairClass('DSI_1')] p10: tolerance=25.4 checknetsindiffpair=TRUE checkdiffpairvsdiffpair=FALSE checkxsignals=FALSE checkothers=FALSE usedelayunits=TRUE delaytolerance=10.000000
MatchedLengths DSI_group [InDifferentialPairClass('DSI')] p11: tolerance=25.4 checknetsindiffpair=FALSE checkdiffpairvsdiffpair=TRUE checkxsignals=TRUE checkothers=TRUE usedelayunits=TRUE delaytolerance=10.000000
MatchedLengths DP_pair [InDifferentialPairClass('DP') or InDifferentialPairClass('DP_CON')] p12: tolerance=25.4 checknetsindiffpair=TRUE checkdiffpairvsdiffpair=FALSE checkxsignals=FALSE checkothers=FALSE usedelayunits=TRUE delaytolerance=5.000000
MatchedLengths DP_group [InDifferentialPairClass('DP')] p13: tolerance=25.4 checknetsindiffpair=FALSE checkdiffpairvsdiffpair=TRUE checkxsignals=TRUE checkothers=TRUE usedelayunits=TRUE delaytolerance=150.000000
MatchedLengths PCIe_pair [InDifferentialPairClass('PCIe_1')   or InDifferentialPairClass('PCIe_2')] p14: tolerance=25.4 checknetsindiffpair=TRUE checkdiffpairvsdiffpair=FALSE checkxsignals=FALSE checkothers=FALSE usedelayunits=TRUE delaytolerance=1.000000
MatchedLengths PCIe_group [InDifferentialPairClass('PCIe_1')   or InDifferentialPairClass('PCIe_2')] p15: tolerance=25.4 checknetsindiffpair=FALSE checkdiffpairvsdiffpair=TRUE checkxsignals=TRUE checkothers=TRUE usedelayunits=TRUE delaytolerance=1600.000000
MatchedLengths ETH_pair [InDifferentialPairClass('ETH1')   or InDifferentialPairClass('ETH2')] p16: tolerance=25.4 checknetsindiffpair=TRUE checkdiffpairvsdiffpair=FALSE checkxsignals=FALSE checkothers=FALSE usedelayunits=TRUE delaytolerance=1.600000
MatchedLengths ETH1_group [InDifferentialPairClass('ETH1')] p17: tolerance=25.4 checknetsindiffpair=FALSE checkdiffpairvsdiffpair=TRUE checkxsignals=TRUE checkothers=TRUE usedelayunits=TRUE delaytolerance=330.000000
MatchedLengths ETH2_group [InDifferentialPairClass('ETH2')] p18: tolerance=25.4 checknetsindiffpair=FALSE checkdiffpairvsdiffpair=TRUE checkxsignals=TRUE checkothers=TRUE usedelayunits=TRUE delaytolerance=330.000000
MatchedLengths XGMII_pair [InDifferentialPairClass('XGMII')   or InDifferentialPairClass('XGMII_PHY')] p19: tolerance=25.4 checknetsindiffpair=TRUE checkdiffpairvsdiffpair=FALSE checkxsignals=FALSE checkothers=FALSE usedelayunits=TRUE delaytolerance=1.000000
MatchedLengths USB_ALL_pairs [InDifferentialPairClass('DFP_SSRX1') or InDifferentialPairClass('DFP_SSRX2') or InDifferentialPairClass('DFP_SSTX1') or InDifferentialPairClass('DFP_SSTX1') or InDifferentialPairClass('DFP_SSTX2') or InDifferentialPairClass('HS_USB_3') or InDifferentialPairClass('PCIEUSB') or InDifferentialPairClass('SSRX1') or InDifferentialPairClass('SSRX2') or InDifferentialPairClass('USB_1_SSTX1') or InDifferentialPairClass('USB_1_SSTX2') or InDifferentialPairClass('USB_2') or InDifferentialPairClass('USB_2_SSRX1') or InDifferentialPairClass('USB_2_SSRX_HUB') or InDifferentialPairClass('USB_2_SSTX1') or InDifferentialPairClass('USB_2_SSTX_HUB') or InDifferentialPairClass('USB_3') or InDifferentialPairClass('USB_3_CON') or InDifferentialPairClass('USB_3_SSRX') or InDifferentialPairClass('USB_3_SSTX') or InDifferentialPairClass('USB_3_SS_HUB') or InDifferentialPairClass('USB_4') or InDifferentialPairClass('USB_4_CON') or InDifferentialPairClass('USB_4_SSRX') or InDifferentialPairClass('USB_4_SSTX') or InDifferentialPairClass('USB_4_SS_HUB') or InDifferentialPairClass('USB_5') or InDifferentialPairClass('USB_5_CON') or InDifferentialPairClass('USB_5_SSRX') or InDifferentialPairClass('USB_5_SSTX') or InDifferentialPairClass('USB_5_SS_HUB') or InDifferentialPairClass('USB_6') or InDifferentialPairClass('USB_6_SSRX') or InDifferentialPairClass('USB_6_SSTX') or InDifferentialPairClass('USB_6_SS_HUB') or InDifferentialPairClass('USB_CYP') or InDifferentialPairClass('USB_FT') or InDifferentialPairClass('USB_FT_CON')] p20: tolerance=25.4 checknetsindiffpair=TRUE checkdiffpairvsdiffpair=FALSE checkxsignals=FALSE checkothers=FALSE usedelayunits=TRUE delaytolerance=1.000000 // Common tolerance for all USB's
MatchedLengths USB_DFP_SS_pair [InDifferentialPairClass('DFP_SSRX1') or InDifferentialPairClass('DFP_SSRX2') or InDifferentialPairClass('DFP_SSTX1') or  InDifferentialPairClass('DFP_SSTX2')] p21: tolerance=25.4 checknetsindiffpair=TRUE checkdiffpairvsdiffpair=FALSE checkxsignals=FALSE checkothers=FALSE usedelayunits=TRUE delaytolerance=1.000000
MatchedLengths USB_Diff.pair_2.0 [InDifferentialPairClass('USB_1') or InDifferentialPairClass('USB_2') or InDifferentialPairClass('USB_3')  or InDifferentialPairClass('USB_4') or InDifferentialPairClass('USB_5') or InDifferentialPairClass('USB_6')  or InDifferentialPairClass('USB_3_CON') or InDifferentialPairClass('USB_4_CON') or InDifferentialPairClass('USB_5_CON') or  InDifferentialPairClass('USB_FT') or InDifferentialPairClass('USB_FT_CON')] p22: tolerance=25.4 checknetsindiffpair=TRUE checkdiffpairvsdiffpair=FALSE checkxsignals=FALSE checkothers=FALSE usedelayunits=TRUE delaytolerance=7.500000
MatchedLengths USB1_SBU_pair [InDifferentialPairClass('USB_1_SBU')] p23: tolerance=25.4 checknetsindiffpair=TRUE checkdiffpairvsdiffpair=FALSE checkxsignals=FALSE checkothers=FALSE usedelayunits=TRUE delaytolerance=1.000000
MatchedLengths USB3_SSRX1_SSTX!_pair [InDifferentialPairClass('USB_3_SSRX1_TX1')] p24: tolerance=25.4 checknetsindiffpair=TRUE checkdiffpairvsdiffpair=FALSE checkxsignals=FALSE checkothers=FALSE usedelayunits=TRUE delaytolerance=1.000000
MatchedLengths USB3_SSRX2_SSTX2_pair [InDifferentialPairClass('USB_3_SSRX2_TX2')] p25: tolerance=25.4 checknetsindiffpair=TRUE checkdiffpairvsdiffpair=FALSE checkxsignals=FALSE checkothers=FALSE usedelayunits=TRUE delaytolerance=1.000000
MatchedLengths xUSB1_2.0_pair [InxSignalClass('USB1_D')] p26: tolerance=25.4 checknetsindiffpair=TRUE checkdiffpairvsdiffpair=FALSE checkxsignals=FALSE checkothers=FALSE usedelayunits=TRUE delaytolerance=5.000000 // Inra-pair skew
MatchedLengths xUSB1_SS_pair [InxSignalClass('USB1_SSRX1') or InxSignalClass('USB1_SSRX2') or InxSignalClass('USB1_SSTX1') or InxSignalClass('USB1_SSTX2')] p27: tolerance=25.4 checknetsindiffpair=TRUE checkdiffpairvsdiffpair=FALSE checkxsignals=FALSE checkothers=FALSE usedelayunits=TRUE delaytolerance=1.000000 // Inra-pair skew
MatchedLengths xUSB2_2.0_pair [InxSignalClass('USB2_D')] p28: tolerance=25.4 checknetsindiffpair=TRUE checkdiffpairvsdiffpair=FALSE checkxsignals=FALSE checkothers=FALSE usedelayunits=TRUE delaytolerance=5.000000
MatchedLengths xUSB2_SS_pair [InxSignalClass('USB2_SSRX') or InxSignalClass('USB2_SSTX')] p29: tolerance=25.4 checknetsindiffpair=TRUE checkdiffpairvsdiffpair=FALSE checkxsignals=FALSE checkothers=FALSE usedelayunits=TRUE delaytolerance=1.000000
MatchedLengths xUSB3_2.0_pair [InxSignalClass('USB3_D')] p30: tolerance=25.4 checknetsindiffpair=TRUE checkdiffpairvsdiffpair=FALSE checkxsignals=FALSE checkothers=FALSE usedelayunits=TRUE delaytolerance=5.000000
MatchedLengths xUSB3_SS_pair [InxSignalClass('USB3_SSRX1') or InxSignalClass('USB3_SSRX2') or InxSignalClass('USB3_SSTX1') or InxSignalClass('USB3_SSTX2')] p31: tolerance=25.4 checknetsindiffpair=TRUE checkdiffpairvsdiffpair=FALSE checkxsignals=FALSE checkothers=FALSE usedelayunits=TRUE delaytolerance=1.000000
MatchedLengths xUSB4_2.0_pair [InxSignalClass('USB4_D')] p32: tolerance=25.4 checknetsindiffpair=TRUE checkdiffpairvsdiffpair=FALSE checkxsignals=FALSE checkothers=FALSE usedelayunits=TRUE delaytolerance=1.000000
MatchedLengths xUSB4_SS_pair [InxSignalClass('USB4_SSRX') or InxSignalClass('USB4_SSTX')] p33: tolerance=25.4 checknetsindiffpair=TRUE checkdiffpairvsdiffpair=FALSE checkxsignals=FALSE checkothers=FALSE usedelayunits=TRUE delaytolerance=1.000000
MatchedLengths xUSB5_2.0_pair [InxSignalClass('USB5_D')] p34: tolerance=25.4 checknetsindiffpair=TRUE checkdiffpairvsdiffpair=FALSE checkxsignals=FALSE checkothers=FALSE usedelayunits=TRUE delaytolerance=1.000000
MatchedLengths xUSB5_SS_pair [InxSignalClass('USB5_SSRX') or InxSignalClass('USB5_SSTX')] p35: tolerance=25.4 checknetsindiffpair=TRUE checkdiffpairvsdiffpair=FALSE checkxsignals=FALSE checkothers=FALSE usedelayunits=TRUE delaytolerance=1.000000
MatchedLengths xUSB6_2.0_pair [InxSignalClass('USB6_D')] p36: tolerance=25.4 checknetsindiffpair=TRUE checkdiffpairvsdiffpair=FALSE checkxsignals=FALSE checkothers=FALSE usedelayunits=TRUE delaytolerance=1.000000
MatchedLengths xUSB6_SS_pair [InxSignalClass('USB6_SSRX') or InxSignalClass('USB6_SSTX')] p37: tolerance=25.4 checknetsindiffpair=TRUE checkdiffpairvsdiffpair=FALSE checkxsignals=FALSE checkothers=FALSE usedelayunits=TRUE delaytolerance=1.000000
MatchedLengths USB_pair_2.0_Xsignal [InxSignalClass('USB1_D') or InxSignalClass('USB3_D')] p38: tolerance=25.4 checknetsindiffpair=TRUE checkdiffpairvsdiffpair=FALSE checkxsignals=FALSE checkothers=FALSE usedelayunits=TRUE delaytolerance=7.500000
MinimumAnnularRing [All] p1: minimumring=0.15
MinimumSolderMaskSliver [not (HasFootprint('T_TORADEX_LOGO') or HasFootprint('GCT_USB4105GFA120'))] p1: minsoldermaskwidth=0.05 // Exclude Toradex logo from the scope
PlaneClearance PlaneClearance_HV [InNetClass('HV')] p1: clearance=0.5
PlaneClearance PlaneClearance_ALL [All] p2: clearance=0.25
PlaneConnect [All] p1: pad.planeconnectstyle=Relief pad.reliefexpansion=0.15 pad.reliefentries=4 pad.reliefconductorwidth=0.35 pad.reliefairgap=0.15 via.planeconnectstyle=Direct via.reliefexpansion=0.3 via.reliefentries=4 via.reliefconductorwidth=0.3 via.reliefairgap=0.15
PolygonConnect Polygon_VIN_L01_U6 [InNamedPolygon('VIN_L01_U6') vs HasFootprint('CAPC3225N') And OnLayer('Top Layer')] p1: connectstyle=Direct reliefconductorwidth=0.254 reliefentries=4 polygonreliefangle="90 Angle" airgapwidth=0.254
PolygonConnect Polygon_3V3 [InNet('3V3') vs HasFootprint('WURTH_61300611821') And OnLayer('INT3_SIG')] p2: connectstyle=Direct reliefconductorwidth=0.254 reliefentries=4 polygonreliefangle="90 Angle" airgapwidth=0.254
PolygonConnect Polygon_3V3_1 [All vs HasFootprint('TESTPOINT_1')] p3: connectstyle=Direct reliefconductorwidth=0.254 reliefentries=4 polygonreliefangle="90 Angle" airgapwidth=0.254
PolygonConnect Polygon_M2M_3V3 [InNet('M2M_3V3')] p4: connectstyle=Direct reliefconductorwidth=0.254 reliefentries=4 polygonreliefangle="90 Angle" airgapwidth=0.254
PolygonConnect Polygon_V+ [InNet('V+')] p5: connectstyle=Direct reliefconductorwidth=0.254 reliefentries=4 polygonreliefangle="90 Angle" airgapwidth=0.254
PolygonConnect Polygon_5V_T_BOT [InNet('5V_T')] p6: connectstyle=Direct reliefconductorwidth=0.254 reliefentries=4 polygonreliefangle="90 Angle" airgapwidth=0.254
PolygonConnect Polygon_SOM [InComponent('M1')] p7: connectstyle=Relief reliefconductorwidth=0.2 reliefentries=4 polygonreliefangle="90 Angle" airgapwidth=0.25
PolygonConnect [All] p8: thpad.connectstyle=Relief thpad.reliefconductorwidth=0.25 thpad.reliefentries=4 thpad.polygonreliefangle="90 Angle" thpad.airgapwidth=0.25 smdpad.connectstyle=Relief smdpad.reliefconductorwidth=0.25 smdpad.reliefentries=4 smdpad.polygonreliefangle="90 Angle" smdpad.airgapwidth=0.25 via.connectstyle=Direct via.reliefconductorwidth=0.3 via.reliefentries=4 via.polygonreliefangle="90 Angle" via.airgapwidth=0.254
RoutingVias [All] p1: holewidth=0.3 width=0.6 viastyle="Through Hole" minholewidth=0.2 minwidth=0.5 maxholewidth=1 maxwidth=1.5
SilkToSilkClearance [All] p1: silktosilkclearance=0
SilkToSolderMaskClearance SilkscreenOverComponentPads [IsPad] p1: minsilkscreentomaskgap=0.07 clearancetoexposedcopper=TRUE
SolderMaskExpansion [All] p1: expansion=0.05 istentingtop=FALSE
SupplyNets "Schematic Supply Nets_48" [InNet('FT_1V8')] p1: voltage=0.000
SupplyNets "Schematic Supply Nets_8" [InNet('D_1V8_LDO')] p2: voltage=0.000
SupplyNets "Schematic Supply Nets_47" [InNet('1V8_ETH2')] p3: voltage=0.000
SupplyNets "Schematic Supply Nets_46" [InNet('V232')] p4: voltage=0.000
SupplyNets "Schematic Supply Nets_45" [InNet('SHLD1')] p5: voltage=0.000
SupplyNets "Schematic Supply Nets_44" [InNet('12V')] p6: voltage=0.000
SupplyNets "Schematic Supply Nets_43" [InNet('VIN_DSI')] p7: voltage=0.000
SupplyNets "Schematic Supply Nets_42" [InNet('M2B_3V3')] p8: voltage=0.000
SupplyNets "Schematic Supply Nets_41" [InNet('1V8_CAN_B')] p9: voltage=0.000
SupplyNets "Schematic Supply Nets_40" [InNet('1V0_ETH2')] p10: voltage=0.000
SupplyNets "Schematic Supply Nets_39" [InNet('GND_ISO1')] p11: voltage=0.000
SupplyNets "Schematic Supply Nets_38" [InNet('3V3')] p12: voltage=0.000
SupplyNets "Schematic Supply Nets_37" [InNet('5V_Mux')] p13: voltage=0.000
SupplyNets "Schematic Supply Nets_36" [InNet('1V2_UHUB')] p14: voltage=0.000
SupplyNets "Schematic Supply Nets_32" [InNet('VIN')] p15: voltage=0.000
SupplyNets "Schematic Supply Nets_31" [InNet('5V')] p16: voltage=0.000
SupplyNets "Schematic Supply Nets_30" [InNet('5V_ISO1')] p17: voltage=0.000
SupplyNets "Schematic Supply Nets_29" [InNet('5V_S')] p18: voltage=0.000
SupplyNets "Schematic Supply Nets_28" [InNet('SHLD4')] p19: voltage=0.000
SupplyNets "Schematic Supply Nets_27" [InNet('5V_CAN_A')] p20: voltage=0.000
SupplyNets "Schematic Supply Nets_26" [InNet('DP_3V3')] p21: voltage=0.000
SupplyNets "Schematic Supply Nets_25" [InNet('1V8')] p22: voltage=0.000
SupplyNets "Schematic Supply Nets_24" [InNet('5V_T')] p23: voltage=0.000
SupplyNets "Schematic Supply Nets_23" [InNet('3V3_SD')] p24: voltage=0.000
SupplyNets "Schematic Supply Nets_22" [InNet('USB4_5V')] p25: voltage=0.000
SupplyNets "Schematic Supply Nets_21" [InNet('5V_STB')] p26: voltage=0.000
SupplyNets "Schematic Supply Nets_20" [InNet('V+')] p27: voltage=0.000
SupplyNets "Schematic Supply Nets_19" [InNet('5V_PD')] p28: voltage=0.000
SupplyNets "Schematic Supply Nets_18" [InNet('USB5_5V')] p29: voltage=0.000
SupplyNets "Schematic Supply Nets_17" [InNet('5V_ISO2')] p30: voltage=0.000
SupplyNets "Schematic Supply Nets_16" [InNet('GND')] p31: voltage=0.000
SupplyNets "Schematic Supply Nets_15" [InNet('M2M_3V3')] p32: voltage=0.000
SupplyNets "Schematic Supply Nets_14" [InNet('V_BUS_PD')] p33: voltage=0.000
SupplyNets "Schematic Supply Nets_13" [InNet('V485')] p34: voltage=0.000
SupplyNets "Schematic Supply Nets_12" [InNet('PGND')] p35: voltage=0.000
SupplyNets "Schematic Supply Nets_11" [InNet('1V8_CAN_A')] p36: voltage=0.000
SupplyNets "Schematic Supply Nets_10" [InNet('FT_3V3')] p37: voltage=0.000
SupplyNets "Schematic Supply Nets_9" [InNet('2V5_ETH2')] p38: voltage=0.000
SupplyNets "Schematic Supply Nets_7" [InNet('VPD')] p39: voltage=0.000
SupplyNets "Schematic Supply Nets_6" [InNet('SHLD2')] p40: voltage=0.000
SupplyNets "Schematic Supply Nets_5" [InNet('3V3_UHUB')] p41: voltage=0.000
SupplyNets "Schematic Supply Nets_4" [InNet('5V_CAN_B')] p42: voltage=0.000
SupplyNets "Schematic Supply Nets_2" [InNet('VDDD_3V3')] p43: voltage=0.000
SupplyNets "Schematic Supply Nets_1" [InNet('SHLD3')] p44: voltage=0.000
SupplyNets "Schematic Supply Nets" [InNet('GND_ISO2')] p45: voltage=0.000
UnRoutedNet [All] p1: checkbadconnections=TRUE
Width Power [InNetClass('Power')] p1: maxlimit=5 minlimit=0.15 preferedwidth=0.5
Width Width_50R [InNetClass('50R')] p2: maxlimit=0.18 minlimit=0.15 preferedwidth=0.18 toplayer_maxwidth=0.15 toplayer_prefwidth=0.15 midlayer6_minwidth=0.18 bottomlayer_maxwidth=0.15 bottomlayer_prefwidth=0.15 impedanceprofiledriven=TRUE impedanceprofileid={6DD104C4-3EC9-4655-8873-C3931F8961BF} impedanceprofilevalue=50.000000 minimp=50.000000 maximp=50.000000 favimp=50.000000
Width Width_All [All] p3: maxlimit=5 minlimit=0.15 preferedwidth=0.18
17 further rules are at their usual default settings.

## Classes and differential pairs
differential pair class USB_5_SS_CON: USB_5_SSRX USB_5_SSTX
differential pair class USB_4_SS_CON: USB_4_SSRX USB_4_SSTX
differential pair class USB_3_MUX_SS2: USB_3_SSRX2 USB_3_SSTX2
differential pair class USB_3_MUX_SS1: USB_3_SSRX1 USB_3_SSTX1
differential pair class USB_6_SS_HUB: USB__6__SSTX
differential pair class USB_5_SS_HUB: USB__5__SSTX
differential pair class USB_4_SS_HUB: USB__4__SSTX
differential pair class USB_3_SS_HUB: USB__3__SSTX
differential pair class USB_2_SSTX_HUB: USB__2__SSTX
differential pair class USB_2_SSRX_HUB: USB__2__SSRX
differential pair class USB_1_SBU: USB_1_SBU
differential pair class USB_1_CON: USB_1_CON
differential pair class PCIEUSB: A0 A1
differential pair class USB_2: USB_2_D
differential pair class USB_1_SSTX2: USB_1_SSTX2
differential pair class USB_1_SSTX1: USB_1_SSTX1
differential pair class USB_1_SSRX2: USB_1_SSRX2
differential pair class USB_1_SSRX1: USB_1_SSRX1
differential pair class USB_3_SSRX: USB3_SSRX
differential pair class DFP_SSRX2: DFP_SSRX2
differential pair class DFP_SSRX1: DFP_SSRX1 DFP_SSRX2
differential pair class DFP_SSTX2: DFP_SSTX2
differential pair class DFP_SSTX1: DFP_SSTX1
differential pair class SSTX2: SSTX2
differential pair class SSTX1: SSTX1
differential pair class SSRX2: SSRX2
differential pair class SSRX1: SSRX1
net class QSPI_RA: NetJ4_2 NetJ4_4 NetJ4_6 NetJ4_8 NetJ4_10 NetJ4_12 NetJ4_14 NetJ4_16 NetJ4_18 NetJ4_20 NetJ4_22 NetJ4_24
net class QSPI_JMP: OSPI_1_IO4_JMP OSPI_1_IO5_JMP OSPI_1_IO6_JMP OSPI_1_IO7_JMP QSPI_1_CS1#_JMP QSPI_1_CS2#_JMP QSPI_1_DQS_JMP QSPI_1_IO0_JMP QSPI_1_IO1_JMP QSPI_1_IO2_JMP QSPI_1_IO3_JMP QSPI_1_SCK_JMP
net class SPI: SPI_1_CLK SPI_1_CS SPI_1_MISO SPI_1_MOSI SPI_2_CLK SPI_2_CS SPI_2_MISO SPI_2_MOSI
net class SD: SD_1_CD# SD_1_CLK SD_1_CMD SD_1_D0 SD_1_D1 SD_1_D2 SD_1_D3
net class QSPI: OSPI_1_IO4 OSPI_1_IO5 OSPI_1_IO6 OSPI_1_IO7 QSPI_1_CS1# QSPI_1_CS2# QSPI_1_DQS QSPI_1_IO0 QSPI_1_IO1 QSPI_1_IO2 QSPI_1_IO3 QSPI_1_SCK
net class HV: NetC5_1 NetC5_2 NetC6_2 NetC7_1 NetD1_2 NetD2_1 NetD2_2 NetD46_1 NetD46_3 NetJ21_2 NetL1_2 NetQ2_5 NetQ16_1 NetQ16_3 NetR1_1 NetR1_2 NetR2_1 NetR2_2 NetR5_1 PGND V+ VIN
differential pair class DP_CON: DP__1_AUX DP__1_LANE0 DP__1_LANE1 DP__1_LANE2 DP__1_LANE3
differential pair class XGMII_PHY: ETH_2_XGMII_CO ETH_2_XGMII_SO
differential pair class MSP: MSP_1_RX MSP_1_TX MSP_2_RX MSP_2_TX MSP_3_RX MSP_3_TX MSP_4_RX MSP_4_TX MSP_5_RX MSP_5_TX MSP_6_RX MSP_6_TX MSP_7_RX MSP_7_TX MSP_8_RX MSP_8_TX MSP_9_RX MSP_9_TX MSP_10_RX MSP_10_TX MSP_11_RX MSP_11_TX MSP_12_RX MSP_12_TX MSP_13_RX MSP_13_TX MSP_14_RX MSP_14_TX MSP_15_RX MSP_15_TX MSP_16_RX MSP_16_TX MSP_17_RX MSP_17_TX
differential pair class XGMII: ETH_2_XGMII_RX ETH_2_XGMII_TX
differential pair class USB_2_SSRX1: USB_2_SSRX1
differential pair class USB_FT_CON: FTUSB
differential pair class USB_FT: FT_USB
differential pair class USB_CYP: CYP USB_CYP
differential pair class USB_5_CON: USB_5
differential pair class USB_4_CON: USB_4
differential pair class USB_3_CON: USB_3
differential pair class ETH2: ETH2_D0 ETH2_D1 ETH2_D2 ETH2_D3
differential pair class DSI_1: DSI_1_CLK DSI_1_D0 DSI_1_D1 DSI_1_D2 DSI_1_D3
differential pair class DSI_1_CON: DSI__CLK DSI__D0 DSI__D1 DSI__D2 DSI__D3
differential pair class CAN: CAN1 CAN2 CAN3 CAN4 CAN_1 CAN_2 CAN_3 CAN_4
differential pair class USB_6: USB6
differential pair class USB_6_SSTX: USB6_SSTX
differential pair class USB_6_SSRX: USB6_SSRX
differential pair class USB_5: USB5
differential pair class USB_5_SSTX: USB5_SSTX
differential pair class USB_5_SSRX: USB5_SSRX
differential pair class USB_4: USB4
differential pair class USB_4_SSTX: USB4_SSTX
differential pair class USB_4_SSRX: USB4_SSRX
differential pair class USB_3_SSTX: USB3_SSTX
differential pair class USB_3: USB3
differential pair class CSI_2: CSI_2_CLK CSI_2_D0 CSI_2_D1 CSI_2_D2 CSI_2_D3
differential pair class CSI_2_CON: CSI_C2_CLK CSI_C2_D0 CSI_C2_D1 CSI_C2_D2 CSI_C2_D3
differential pair class PCIe_2: PCIE_2_CLK PCIE_2_L0_RX PCIE_2_L0_TX PCIE_2_L1_RX PCIE_2_L1_TX
differential pair class PCIe_1: PCIE_1_CLK PCIE_1_L0_RX PCIE_1_L0_TX PCIE_1_L1_RX PCIE_1_L1_TX
differential pair class ETH1: ETH_1_MDI0 ETH_1_MDI1 ETH_1_MDI2 ETH_1_MDI3
component class 900_Display_Port: C345 C346 C347 C348 C349 C350 J27 L75 L76 L100 L101 L102 L103 R115 R217 R218 R256 R267 R270 R393 R399 R438 R439 R440 R441 U46 U47 U53 U80 X16 X25
differential pair class USB_2_SSTX1: USB_2_SSTX1
component class 810_Jumpers: J7 J7A J7B J8 J8A J8B J9 J9A J9B J10 J10A J10B J11 J11A J11B J12 J12A J12B J13 J92 R413 R414 R426 R427 R477 R478 RA15 RA22 RA30 RA33 RA34 RA36 RA38 RA39 RA40 RA45
component class 800_Jumpers: J1 J1A J1B J2 J2A J2B J3 J3A J3B J4 J4A J4B J5 J5A J5B J6 J6A J6B J14 J14A J14B R75 R76 R409 R410 R411 R412 RA1 RA11 RA14 RA16 RA17 RA18 RA19 RA20 RA21 RA23 RA24 RA25 RA26 RA27 RA28 RA29 RA31 RA32 RA35
component class 700_RS232_RS485: C302 C303 C304 C305 C306 C307 C308 C309 C310 J18 J20 J66 J67 J87 L78 L79 L80 R343 R344 R345 R346 R348 R349 R350 R382 R383 R384 R385 R407 R432 U45 U76 U77
component class 540_Audio: C144 C182 C184 C189 C217 C218 C219 C220 C221 C222 C223 C224 C225 C226 C227 C326 C327 C333 C334 C335 C336 C337 C338 C339 C340 C341 C342 J46 J69 JP2 L10 L11 L12 L43 L45 L60 L61 R192 R212 R214 R215 R216 R297 R299 R300 R302 R340 R419 R420 R421 R422 R423 RA37 RA41 U43 U52 U78 U79 X71 X72 X75 X115
component class 450_CSI_2: C317 C318 C319 C320 C321 C322 J71 L86 L87 L88 L89 L90 R367 R368 R369 R370 R371 R372 R373 R374 U88 U89
component class 445_CSI_1: C311 C312 C313 C314 C315 C316 J70 L81 L82 L83 L84 L85 R359 R360 R361 R362 R363 R364 R365 R366 U81 U82
component class 350_Ethernet: C148 J34 R146 R147 R148 U33 U34
component class 310_USB3: C32 C33 C139 C140 C145 C146 C190 C191 C198 C199 C330 D20 D21 D37 D38 J33 L32 L33 L34 L35 L36 L37 L38 L39 R138 R139 R140 R141 R142 R143 R144 R145 R220 R298 R354 R355 R398 U28 U29 U30 U31 U32 X48 X49 X50 X51 X52 X53
component class 230_SD_Card: C90 C91 C280 C282 D14 J30 L20 R96 R97 R98 R99 R210 R460 U16 U17 U18 X31 X32
component class 200_Aquila: C51 C52 C53 C54 C55 C56 C57 C58 C59 C60 C61 C62 C63 C64 J94 J95 J96 J97 M1 ME5 ME6 ME7 ME8 ME9 ME10 ME11 ME12 R65 R66 R352 R459
component class 140_Power_3: C8 C9 C10 C11 C12 D5 J22 Q3 Q4 R12 R13 R14 R15 R16 R17 R18 R19 R20 R21 R22 R23 R24 R25 R26 U3 U4 X10 X11 X12
differential pair class USB_1: USB_1_D
differential pair class DP: DP_1_AUX DP_1_LANE0 DP_1_LANE1 DP_1_LANE2 DP_1_LANE3
differential pair class CSI_1_CON: CSI_C1_CLK CSI_C1_D0 CSI_C1_D1 CSI_C1_D2 CSI_C1_D3
component class 315_USBC_DFP: C35 C323 C324 C325 C328 C329 C344 D36 D45 J72 J93 L91 L92 L94 L95 L96 L97 L99 Q28 R375 R376 R377 R379 R386 R387 R389 R390 R391 R392 R394 R396 R397 R401 R405 R433 R434 R435 R436 R437 U95 U96 U97 U98 U99 U100 X98 X99 X100 X101 X102 X103 X104 X105 X106 X107 X112
component class 325_USB_PowerDelivery: C284 C285 C287 C288 C289 C290 C291 C292 C293 C294 C295 C296 C297 C298 C299 C300 C301 D24 D28 D44 F2 J65 J88 L77 Q21 Q24 Q26 Q27 R313 R314 R315 R316 R317 R319 R320 R321 R323 R324 R325 R326 R327 R328 R329 R330 R331 R332 R333 R334 R335 R336 R337 R338 R339 R342 R388 R402 R403 U74 U75 U104 X91 X92 X93 X94 X95 X96 X110 X113 X114
component class 160_Power_4: C180 C181 C183 C185 C187 C265 C266 C267 C268 C269 C270 C271 C272 C273 C274 C275 C276 C277 C278 C279 C281 C283 D43 D49 L9 Q22 Q23 R303 R304 R305 R306 R307 R309 R310 R311 R312 R318 R431 U73 X86 X87 X89 X90
component class 620_Peripherals2: B1 B2 B3 B4 C234 C235 C236 C237 D39 D40 D41 D42 J50 J51 J52 J53 J54 J55 J56 J76 J91 Q17 Q18 Q19 R240 R241 R242 R243 R244 R245 R246 R247 R248 R249 R250 R251 R252 R253 R254 R255 R257 R258 R259 R260 R261 R262 R263 R264 R265 R266 R268 R269 R271 R272 R273 R274 R275 R276 R277 R278 R279 R280 R281 R282 S1 S2 S3 S4 U25 U40 U57 U58 X80
component class 600_Peripherals: B7 B8 C228 C229 C230 C231 C232 C233 C360 D33 D34 D35 J48 L62 L63 R221 R222 R223 R224 R225 R226 R227 R228 R229 R230 R231 R232 R233 R234 R235 R236 R237 R238 R239 R358 RA5 RA6 RA7 U54 U55 U56 X73 X74 X76 XB1
component class 500_CAN: C209 C210 C211 C212 C213 C214 C215 C216 J29 J45 J49 J64 J77 J78 J79 J80 J81 J82 L56 L57 L58 L59 R43 R50 R205 R206 R207 R208 R356 R357 U48 U49 U50 U51
component class 510_ISO_CAN: C247 C248 C249 C250 C251 C252 C253 C254 C255 C256 C257 C258 C259 C260 C261 C262 C263 C264 C356 C357 J68 J73 J74 J75 J83 J84 J85 J86 J89 J90 L71 L72 L73 L74 R67 R68 R289 R290 R291 R292 R293 R294 R295 R296 R380 R381 U65 U66 U67 U68 U69 U70 U71 U72 X82 X83 X84 X85
component class 410_M2_KeyM: C200 C201 C202 C203 C370 C371 C372 C373 C374 C375 C376 C377 C378 C379 C380 C381 C382 C383 C384 C385 C386 C387 C388 D27 D29 D30 D47 J43 J62 L48 L49 ME18 R198 R199 R200 R202 R203 R204 R341 R406 R417 X66 X67 X68 X69 X70
component class 420_MIPI_DSI: C204 C205 C206 C207 C208 C359 D31 J44 JP3 JP4 L50 L51 L52 L53 L54 L55 ME1 ME2 ME3 ME4 R408 R468 R469 R470 R471 R472 R473 R474 R475 R476 U85
component class 400_M2_KeyB: C192 C193 C194 C195 C196 C197 C286 C358 C361 C362 C363 C364 C365 C366 C367 C368 C369 D23 D25 D26 D32 J37 J38 J39 J40 J41 J42 L46 L47 ME13 ME14 ME15 Q6 R181 R182 R183 R184 R185 R186 R187 R188 R190 R191 R193 R194 R195 R196 R197 R301 R308 R322 R378 R418 U41 U42 U63 X27 X60 X61 X62 X63 X64 X65 X111
component class 360_Ethernet2: C96 C98 C99 C130 C141 C142 C143 C147 C149 C150 C151 C152 C153 C154 C155 C156 C157 C158 C159 C160 C161 C162 C163 C164 C165 C166 C167 C168 C169 C170 C171 C172 C173 C174 C175 C176 C177 C178 C179 C186 C188 D22 J28 J35 J36 L41 L42 Q15 Q30 R61 R62 R63 R121 R149 R150 R151 R152 R153 R154 R155 R156 R157 R158 R159 R160 R161 R162 R163 R164 R165 R166 R167 R168 R169 R170 R171 R172 R173 R174 R175 R176 R177 R178 R179 R180 R219 R400 R450 R451 U35 U36 U37 U38 U39 X54 X55 X56 X57 X59 Y2
component class 305_USB_Hub: C102 C103 C104 C105 C106 C107 C108 C109 C110 C111 C112 C113 C114 C115 C116 C117 C118 C119 C120 C121 C122 C123 C124 C125 C126 C127 C128 C129 C131 C132 C133 C134 C135 C136 C137 C138 D19 L31 Q13 Q14 R122 R123 R124 R125 R126 R127 R128 R129 R130 R131 R132 R133 R134 R135 R136 R137 R213 R353 R461 R462 RA4 U26 U27 X42 X43 X45 X46 X47 Y3
component class 300_USB1_OTG: C28 C31 C92 C93 C94 C95 C97 C100 C101 C343 C355 D16 D17 D18 D50 J31 J32 JP1 L21 L22 L23 L26 L28 L29 L30 Q12 Q29 R100 R101 R102 R103 R104 R105 R106 R107 R108 R109 R110 R111 R112 R113 R114 R116 R117 R118 R119 R120 R395 R404 R452 U19 U20 U21 U22 U23 U24 U84 X33 X34 X36 X37 X38 X39 X41
component class 225_Debug2: C74 C75 C76 C77 C78 C79 C80 C81 C82 C83 C84 C85 C86 C87 C88 C89 C353 C354 C389 C390 C391 C392 C393 C394 D10 D13 J19 J24 J25 J26 J63 L16 L17 L18 L19 Q9 Q10 Q11 Q31 Q32 R86 R87 R88 R89 R90 R91 R92 R93 R94 R95 R189 R453 R454 R455 R456 R457 R458 R467 RA3 U14 U15 U60 U87 Y1
component class 220_Debug: C39 C41 C71 C72 C73 D11 D12 J23 L13 L14 L15 R80 R81 R82 R83 R84 R85 U12 U13 U86 X29 X30
component class 210_Translators: C65 C66 C67 C68 C69 C70 R69 R70 R71 R72 R73 R74 R77 R78 R79 U9 U10 U11
component class 227_JTAG: C238 C239 C240 J57 J58 J59 L66 R283 R284 R285 R286 R287 R288 R463 R464 U59 U61
component class 120_Power_2: B5 B6 C13 C14 C15 C16 C17 C18 C19 C20 C21 C22 C23 C24 C25 C26 C27 C29 C30 C34 C36 C37 C38 C40 C42 C43 C44 C45 C46 C47 C48 C49 C50 C331 C332 D6 D7 D8 D9 D15 D48 IC1 J47 L4 L5 L6 Q5 Q7 Q8 R27 R28 R29 R30 R31 R32 R33 R34 R35 R36 R37 R38 R39 R40 R41 R42 R44 R45 R46 R47 R48 R49 R51 R52 R53 R54 R55 R56 R57 R58 R59 R60 R64 R430 R465 U5 U6 U7 U8 X13 X14 X15 X17 X18 X19 X20 X21 X22 X23 X24 X28
component class 100_Power_1: C1 C2 C3 C4 C5 C6 C7 D1 D2 D3 D4 D46 F1 J15 J16 J17 J21 L1 Q1 Q2 Q16 Q25 R1 R2 R3 R4 R5 R6 R7 R8 R9 R10 R11 R347 R351 R447 R448 R449 U1 U2 X1 X2 X3 X4 X5 X6 X7 X8 X9 X108 X109
component class 215_Translators2: C241 C242 C243 C244 C245 C246 C351 C352 J60 J61 R442 R443 R444 R445 R446 RA8 RA9 RA10 U44 U62 U64 U83
component class 000_Main: FID1 FID2 FID3 FID4 FID5 FID6 H1 H2 H3 H4 LBL1 MP1 MP2 MP3 MP4 MP5 MP6 MP7 MP8 MP9 MP10
differential pair class DSI: DSI_1_CLK DSI_1_CLK_CON DSI_1_D0 DSI_1_D0_CON DSI_1_D1 DSI_1_D1_CON DSI_1_D2 DSI_1_D2_CON DSI_1_D3 DSI_1_D3_CON
differential pair class CSI_1: CSI_1_CLK CSI_1_D0 CSI_1_D1 CSI_1_D2 CSI_1_D3
differential pair class USB: USB_1_CON USB_1_D USB_1_SBU USB_1_SSRX1 USB_1_SSRX2 USB_1_SSTX1 USB_1_SSTX2 USB_2_D USB_2_SSRX1 USB_2_SSTX1
net class 50R: CAM_1_CON_MCLK CAM_2_CON_MCLK CTRL_MCLK_3V NetJ4_2 NetJ4_4 NetJ4_6 NetJ4_8 NetJ4_10 NetJ4_12 NetJ4_14 NetJ4_16 NetJ4_18 NetJ4_20 NetJ4_22 NetJ4_24 OSPI_1_IO4 OSPI_1_IO4_JMP OSPI_1_IO5 OSPI_1_IO5_JMP OSPI_1_IO6 OSPI_1_IO6_JMP OSPI_1_IO7 OSPI_1_IO7_JMP QSPI_1_CS1# QSPI_1_CS1#_JMP QSPI_1_CS2# QSPI_1_CS2#_JMP QSPI_1_DQS QSPI_1_DQS_JMP QSPI_1_IO0 QSPI_1_IO0_JMP QSPI_1_IO1 QSPI_1_IO1_JMP QSPI_1_IO2 QSPI_1_IO2_JMP QSPI_1_IO3 QSPI_1_IO3_JMP QSPI_1_SCK QSPI_1_SCK_JMP SD_1_CD# SD_1_CLK SD_1_CMD SD_1_D0 SD_1_D1 SD_1_D2 SD_1_D3 SPI_1_CLK SPI_1_CS SPI_1_MISO SPI_1_MOSI SPI_2_CLK SPI_2_CS SPI_2_MISO SPI_2_MOSI
differential pair USB__6__SSTX: +USB__6__SSTX_P -USB__6__SSTX_N
differential pair USB__5__SSTX: +USB__5__SSTX_P -USB__5__SSTX_N
differential pair USB__4__SSTX: +USB__4__SSTX_P -USB__4__SSTX_N
differential pair USB__3__SSTX: +USB__3__SSTX_P -USB__3__SSTX_N
differential pair USB__2__SSTX: +USB__2__SSTX_P -USB__2__SSTX_N
differential pair USB__2__SSRX: +USB__2__SSRX_P -USB__2__SSRX_N
differential pair ETH_2_XGMII_CO: +ETH_2_XGMII_CO_P -ETH_2_XGMII_CO_N
differential pair USB_1_SBU: +USB_1_SBU_P -USB_1_SBU_N
differential pair USB_1_CON: +USB_1_CON_P -USB_1_CON_N
differential pair ETH_2_XGMII_SO: +ETH_2_XGMII_SO_P -ETH_2_XGMII_SO_N
differential pair MSP_17_TX: +MSP_17_TX_P -MSP_17_TX_N
differential pair MSP_17_RX: +MSP_17_RX_P -MSP_17_RX_N
differential pair MSP_16_TX: +MSP_16_TX_P -MSP_16_TX_N
differential pair MSP_16_RX: +MSP_16_RX_P -MSP_16_RX_N
differential pair MSP_15_TX: +MSP_15_TX_P -MSP_15_TX_N
differential pair MSP_15_RX: +MSP_15_RX_P -MSP_15_RX_N
differential pair MSP_14_TX: +MSP_14_TX_P -MSP_14_TX_N
differential pair MSP_14_RX: +MSP_14_RX_P -MSP_14_RX_N
differential pair MSP_13_TX: +MSP_13_TX_P -MSP_13_TX_N
differential pair MSP_13_RX: +MSP_13_RX_P -MSP_13_RX_N
differential pair MSP_12_TX: +MSP_12_TX_P -MSP_12_TX_N
differential pair MSP_12_RX: +MSP_12_RX_P -MSP_12_RX_N
differential pair MSP_11_TX: +MSP_11_TX_P -MSP_11_TX_N
differential pair MSP_11_RX: +MSP_11_RX_P -MSP_11_RX_N
differential pair MSP_10_TX: +MSP_10_TX_P -MSP_10_TX_N
differential pair MSP_10_RX: +MSP_10_RX_P -MSP_10_RX_N
differential pair MSP_9_TX: +MSP_9_TX_P -MSP_9_TX_N
differential pair MSP_9_RX: +MSP_9_RX_P -MSP_9_RX_N
differential pair MSP_8_TX: +MSP_8_TX_P -MSP_8_TX_N
differential pair MSP_8_RX: +MSP_8_RX_P -MSP_8_RX_N
differential pair MSP_7_TX: +MSP_7_TX_P -MSP_7_TX_N
differential pair MSP_7_RX: +MSP_7_RX_P -MSP_7_RX_N
differential pair MSP_6_TX: +MSP_6_TX_P -MSP_6_TX_N
differential pair MSP_6_RX: +MSP_6_RX_P -MSP_6_RX_N
differential pair MSP_5_TX: +MSP_5_TX_P -MSP_5_TX_N
differential pair MSP_5_RX: +MSP_5_RX_P -MSP_5_RX_N
differential pair MSP_4_TX: +MSP_4_TX_P -MSP_4_TX_N
differential pair MSP_4_RX: +MSP_4_RX_P -MSP_4_RX_N
differential pair MSP_3_TX: +MSP_3_TX_P -MSP_3_TX_N
differential pair MSP_3_RX: +MSP_3_RX_P -MSP_3_RX_N
differential pair MSP_2_TX: +MSP_2_TX_P -MSP_2_TX_N
differential pair MSP_2_RX: +MSP_2_RX_P -MSP_2_RX_N
differential pair MSP_1_TX: +MSP_1_TX_P -MSP_1_TX_N
differential pair MSP_1_RX: +MSP_1_RX_P -MSP_1_RX_N
differential pair USB_1_SSRX1: +USB_1_SSRX1_P -USB_1_SSRX1_N
differential pair USB_2_SSTX1: +USB_2_SSTX1_P -USB_2_SSTX1_N
differential pair USB_2_SSRX1: +USB_2_SSRX1_P -USB_2_SSRX1_N
differential pair USB_1_SSTX2: +USB_1_SSTX2_P -USB_1_SSTX2_N
differential pair USB_1_SSRX2: +USB_1_SSRX2_P -USB_1_SSRX2_N
differential pair ETH_2_XGMII_TX: +ETH_2_XGMII_TX_P -ETH_2_XGMII_TX_N
differential pair ETH_2_XGMII_RX: +ETH_2_XGMII_RX_P -ETH_2_XGMII_RX_N
differential pair CYP: +CYP_P -CYP_N
differential pair USB_CYP: +USB_CYP_P -USB_CYP_N
differential pair CAN_4: +CAN_4_P -CAN_4_N
differential pair CAN_3: +CAN_3_P -CAN_3_N
differential pair CAN_2: +CAN_2_P -CAN_2_N
differential pair CAN_1: +CAN_1_P -CAN_1_N
differential pair CAN4: +CAN4_P -CAN4_N
differential pair CAN3: +CAN3_P -CAN3_N
differential pair CAN2: +CAN2_P -CAN2_N
differential pair CAN1: +CAN1_P -CAN1_N
differential pair DP__1_LANE3: +DP__1_LANE3_P -DP__1_LANE3_N
differential pair DP__1_LANE2: +DP__1_LANE2_P -DP__1_LANE2_N
differential pair DP__1_LANE1: +DP__1_LANE1_P -DP__1_LANE1_N
differential pair DP__1_LANE0: +DP__1_LANE0_P -DP__1_LANE0_N
differential pair DP__1_AUX: +DP__1_AUX_P -DP__1_AUX_N
differential pair USB6: +USB6_P -USB6_N
differential pair USB6_SSRX: +USB6_SSRX_P -USB6_SSRX_N
differential pair USB5: +USB5_P -USB5_N
differential pair USB5_SSRX: +USB5_SSRX_P -USB5_SSRX_N
differential pair USB4: +USB4_P -USB4_N
differential pair USB4_SSRX: +USB4_SSRX_P -USB4_SSRX_N
differential pair USB3: +USB3_P -USB3_N
differential pair USB3_SSRX: +USB3_SSRX_P -USB3_SSRX_N
differential pair USB_3_SSTX1: +USB_3_SSTX1_P -USB_3_SSTX1_N
differential pair USB6_SSTX: +USB6_SSTX_P -USB6_SSTX_N
differential pair DFP_SSTX1: +DFP_SSTX1_P -DFP_SSTX1_N
differential pair DFP_SSRX1: +DFP_SSRX1_P -DFP_SSRX1_N
differential pair A1: +A1_P -A1_N
differential pair USB_3: +USB_3_P -USB_3_N
differential pair USB_3_SSTX2: +USB_3_SSTX2_P -USB_3_SSTX2_N
differential pair USB_3_SSRX2: +USB_3_SSRX2_P -USB_3_SSRX2_N
differential pair USB_3_SSRX1: +USB_3_SSRX1_P -USB_3_SSRX1_N
differential pair USB3_SSTX: +USB3_SSTX_P -USB3_SSTX_N
differential pair DFP_SSTX2: +DFP_SSTX2_P -DFP_SSTX2_N
differential pair DFP_SSRX2: +DFP_SSRX2_P -DFP_SSRX2_N
differential pair A0: +A0_P -A0_N
differential pair USB_5: +USB_5_P -USB_5_N
differential pair USB_5_SSTX: +USB_5_SSTX_P -USB_5_SSTX_N
differential pair USB_5_SSRX: +USB_5_SSRX_P -USB_5_SSRX_N
differential pair USB_4: +USB_4_P -USB_4_N
differential pair USB_4_SSTX: +USB_4_SSTX_P -USB_4_SSTX_N
differential pair USB_4_SSRX: +USB_4_SSRX_P -USB_4_SSRX_N
differential pair USB_1_SSTX1: +USB_1_SSTX1_P -USB_1_SSTX1_N
differential pair USB5_SSTX: +USB5_SSTX_P -USB5_SSTX_N
differential pair USB4_SSTX: +USB4_SSTX_P -USB4_SSTX_N
differential pair SSTX2: +SSTX2_P -SSTX2_N
differential pair SSTX1: +SSTX1_P -SSTX1_N
differential pair SSRX2: +SSRX2_P -SSRX2_N
differential pair SSRX1: +SSRX1_P -SSRX1_N
differential pair PCIE_2_L1_TX: +PCIE_2_L1_TX_P -PCIE_2_L1_TX_N
differential pair PCIE_2_L1_RX: +PCIE_2_L1_RX_P -PCIE_2_L1_RX_N
differential pair PCIE_2_L0_TX: +PCIE_2_L0_TX_P -PCIE_2_L0_TX_N
differential pair PCIE_2_L0_RX: +PCIE_2_L0_RX_P -PCIE_2_L0_RX_N
differential pair PCIE_2_CLK: +PCIE_2_CLK_P -PCIE_2_CLK_N
differential pair PCIE_1_L1_TX: +PCIE_1_L1_TX_P -PCIE_1_L1_TX_N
